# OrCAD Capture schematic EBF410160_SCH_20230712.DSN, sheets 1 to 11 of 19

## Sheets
1 12 WLAN BT: size A4; title: 野火_EBF RK3566 BTB 底板; rev: V1.0; note: WLAN & BT; note: https://yehuosm.tmall.com
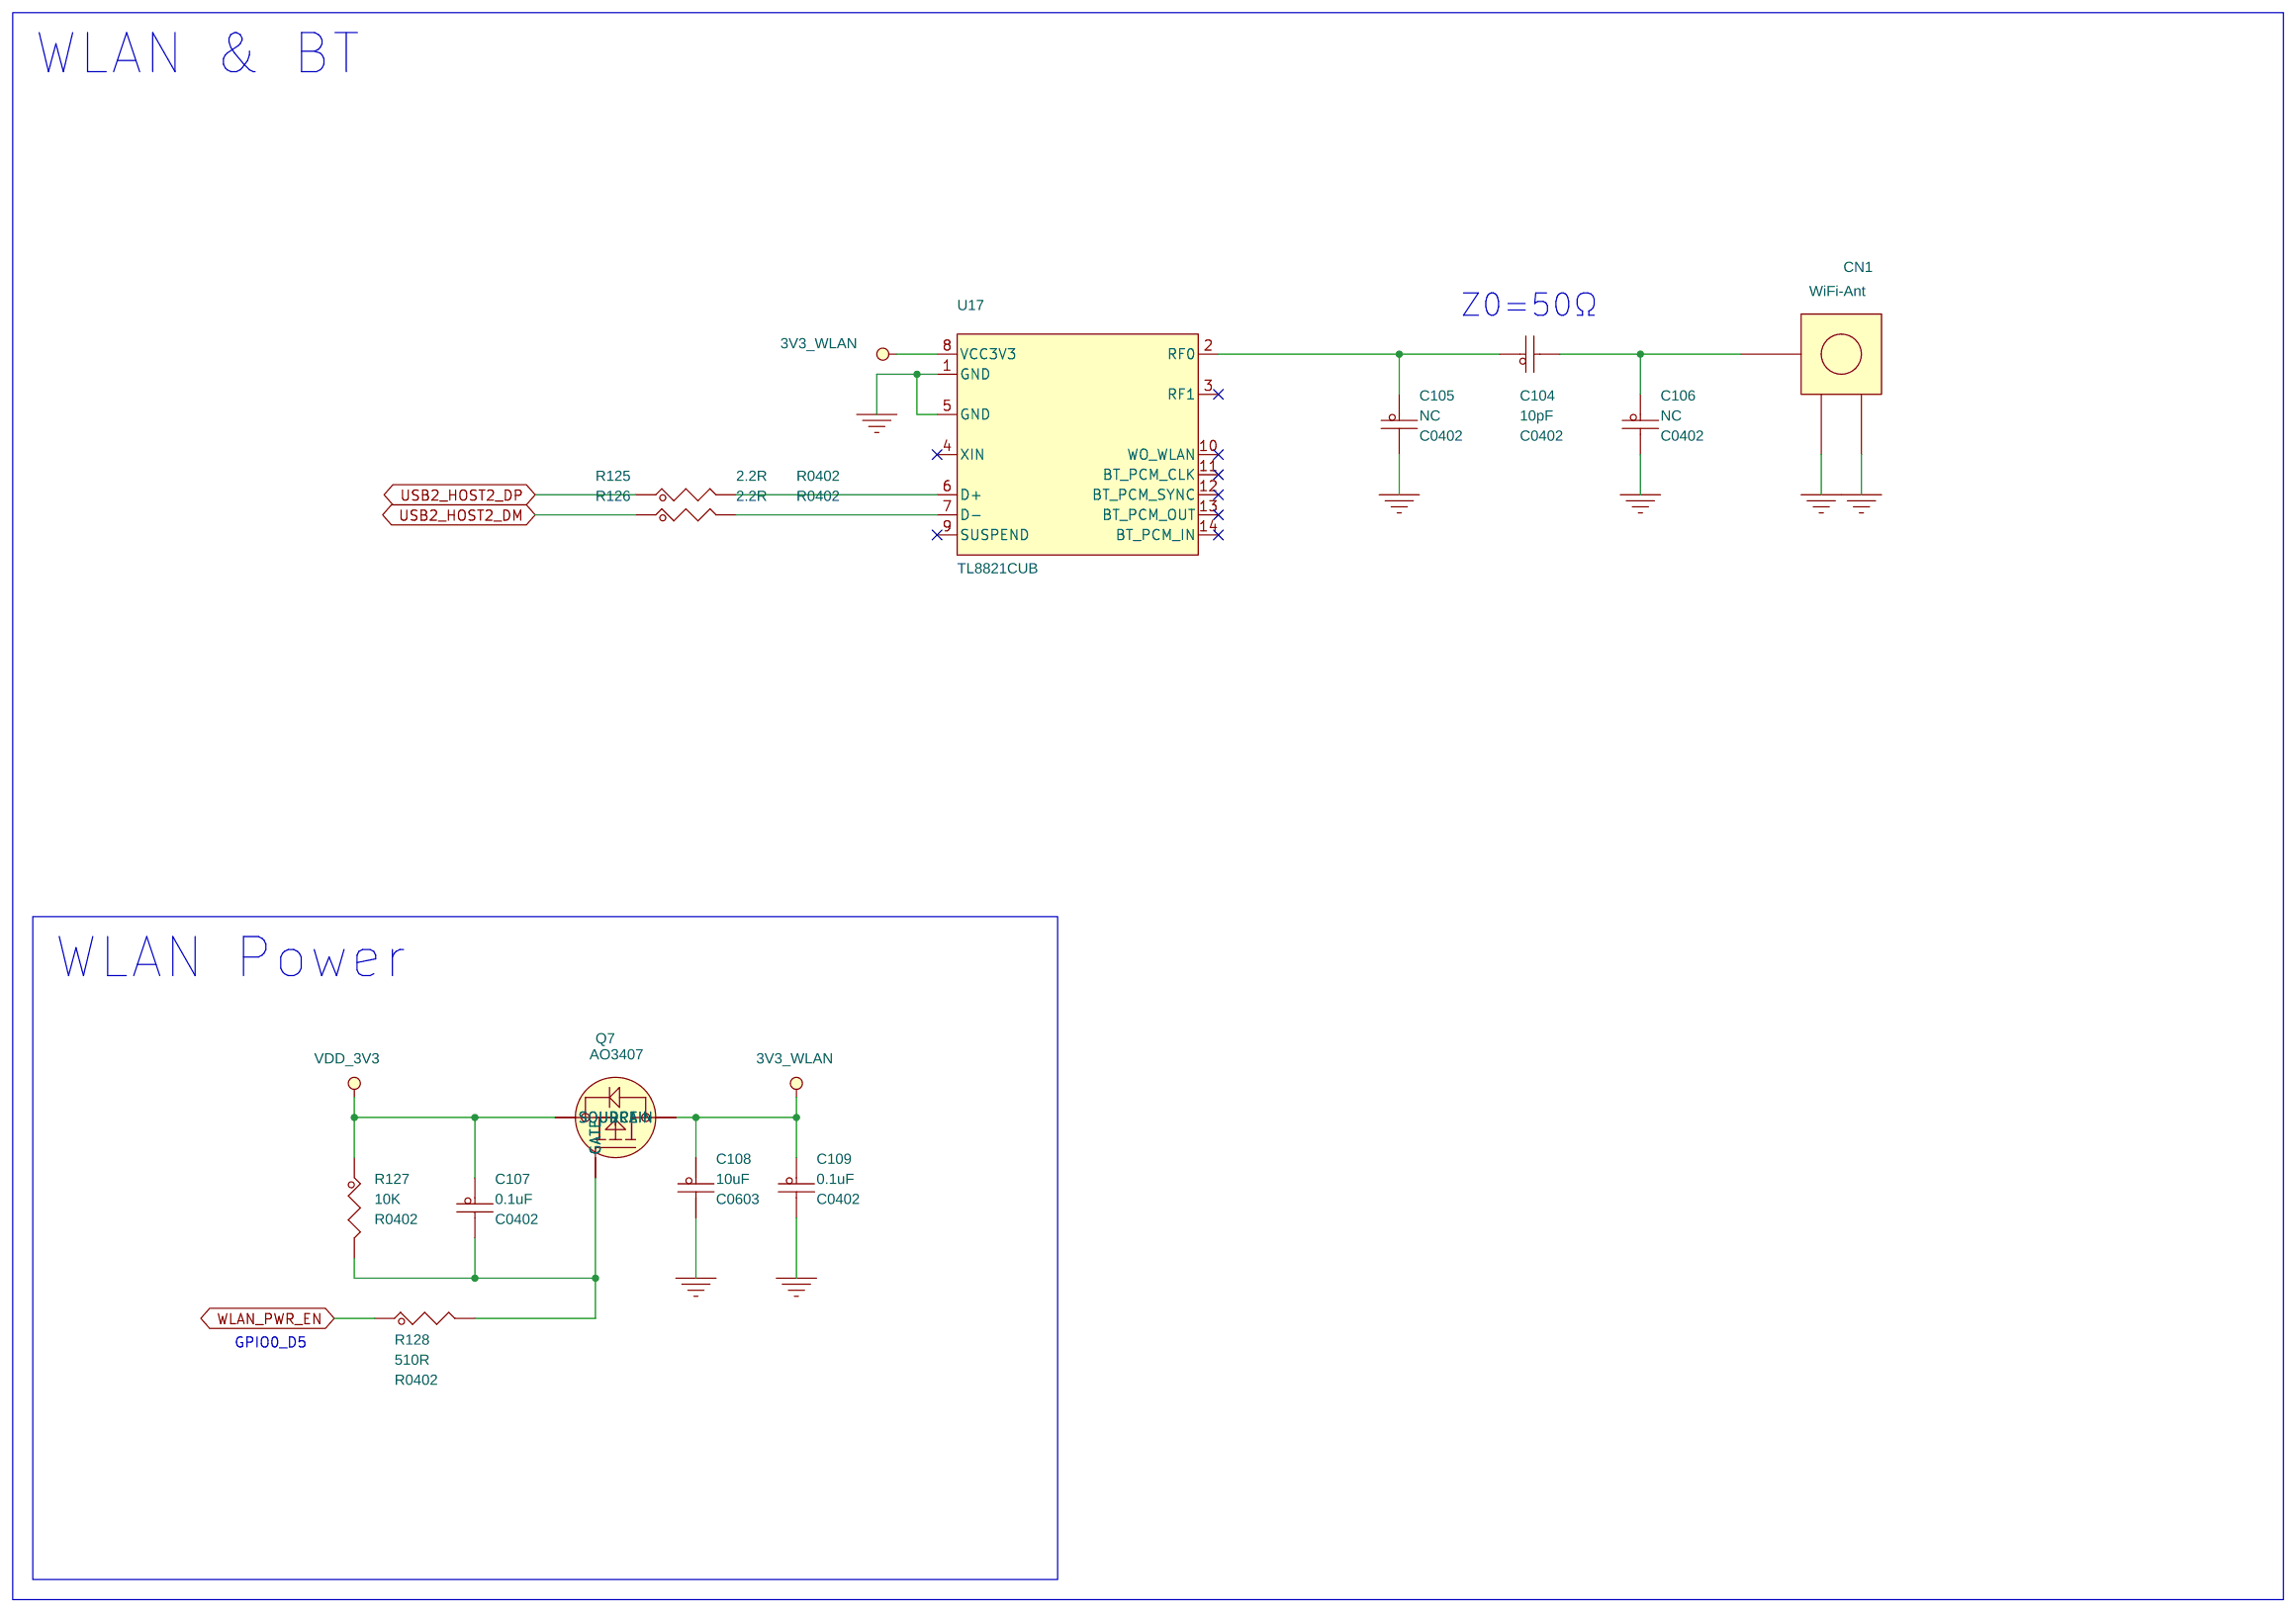
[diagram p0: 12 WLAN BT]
2 01 Content: note: Content
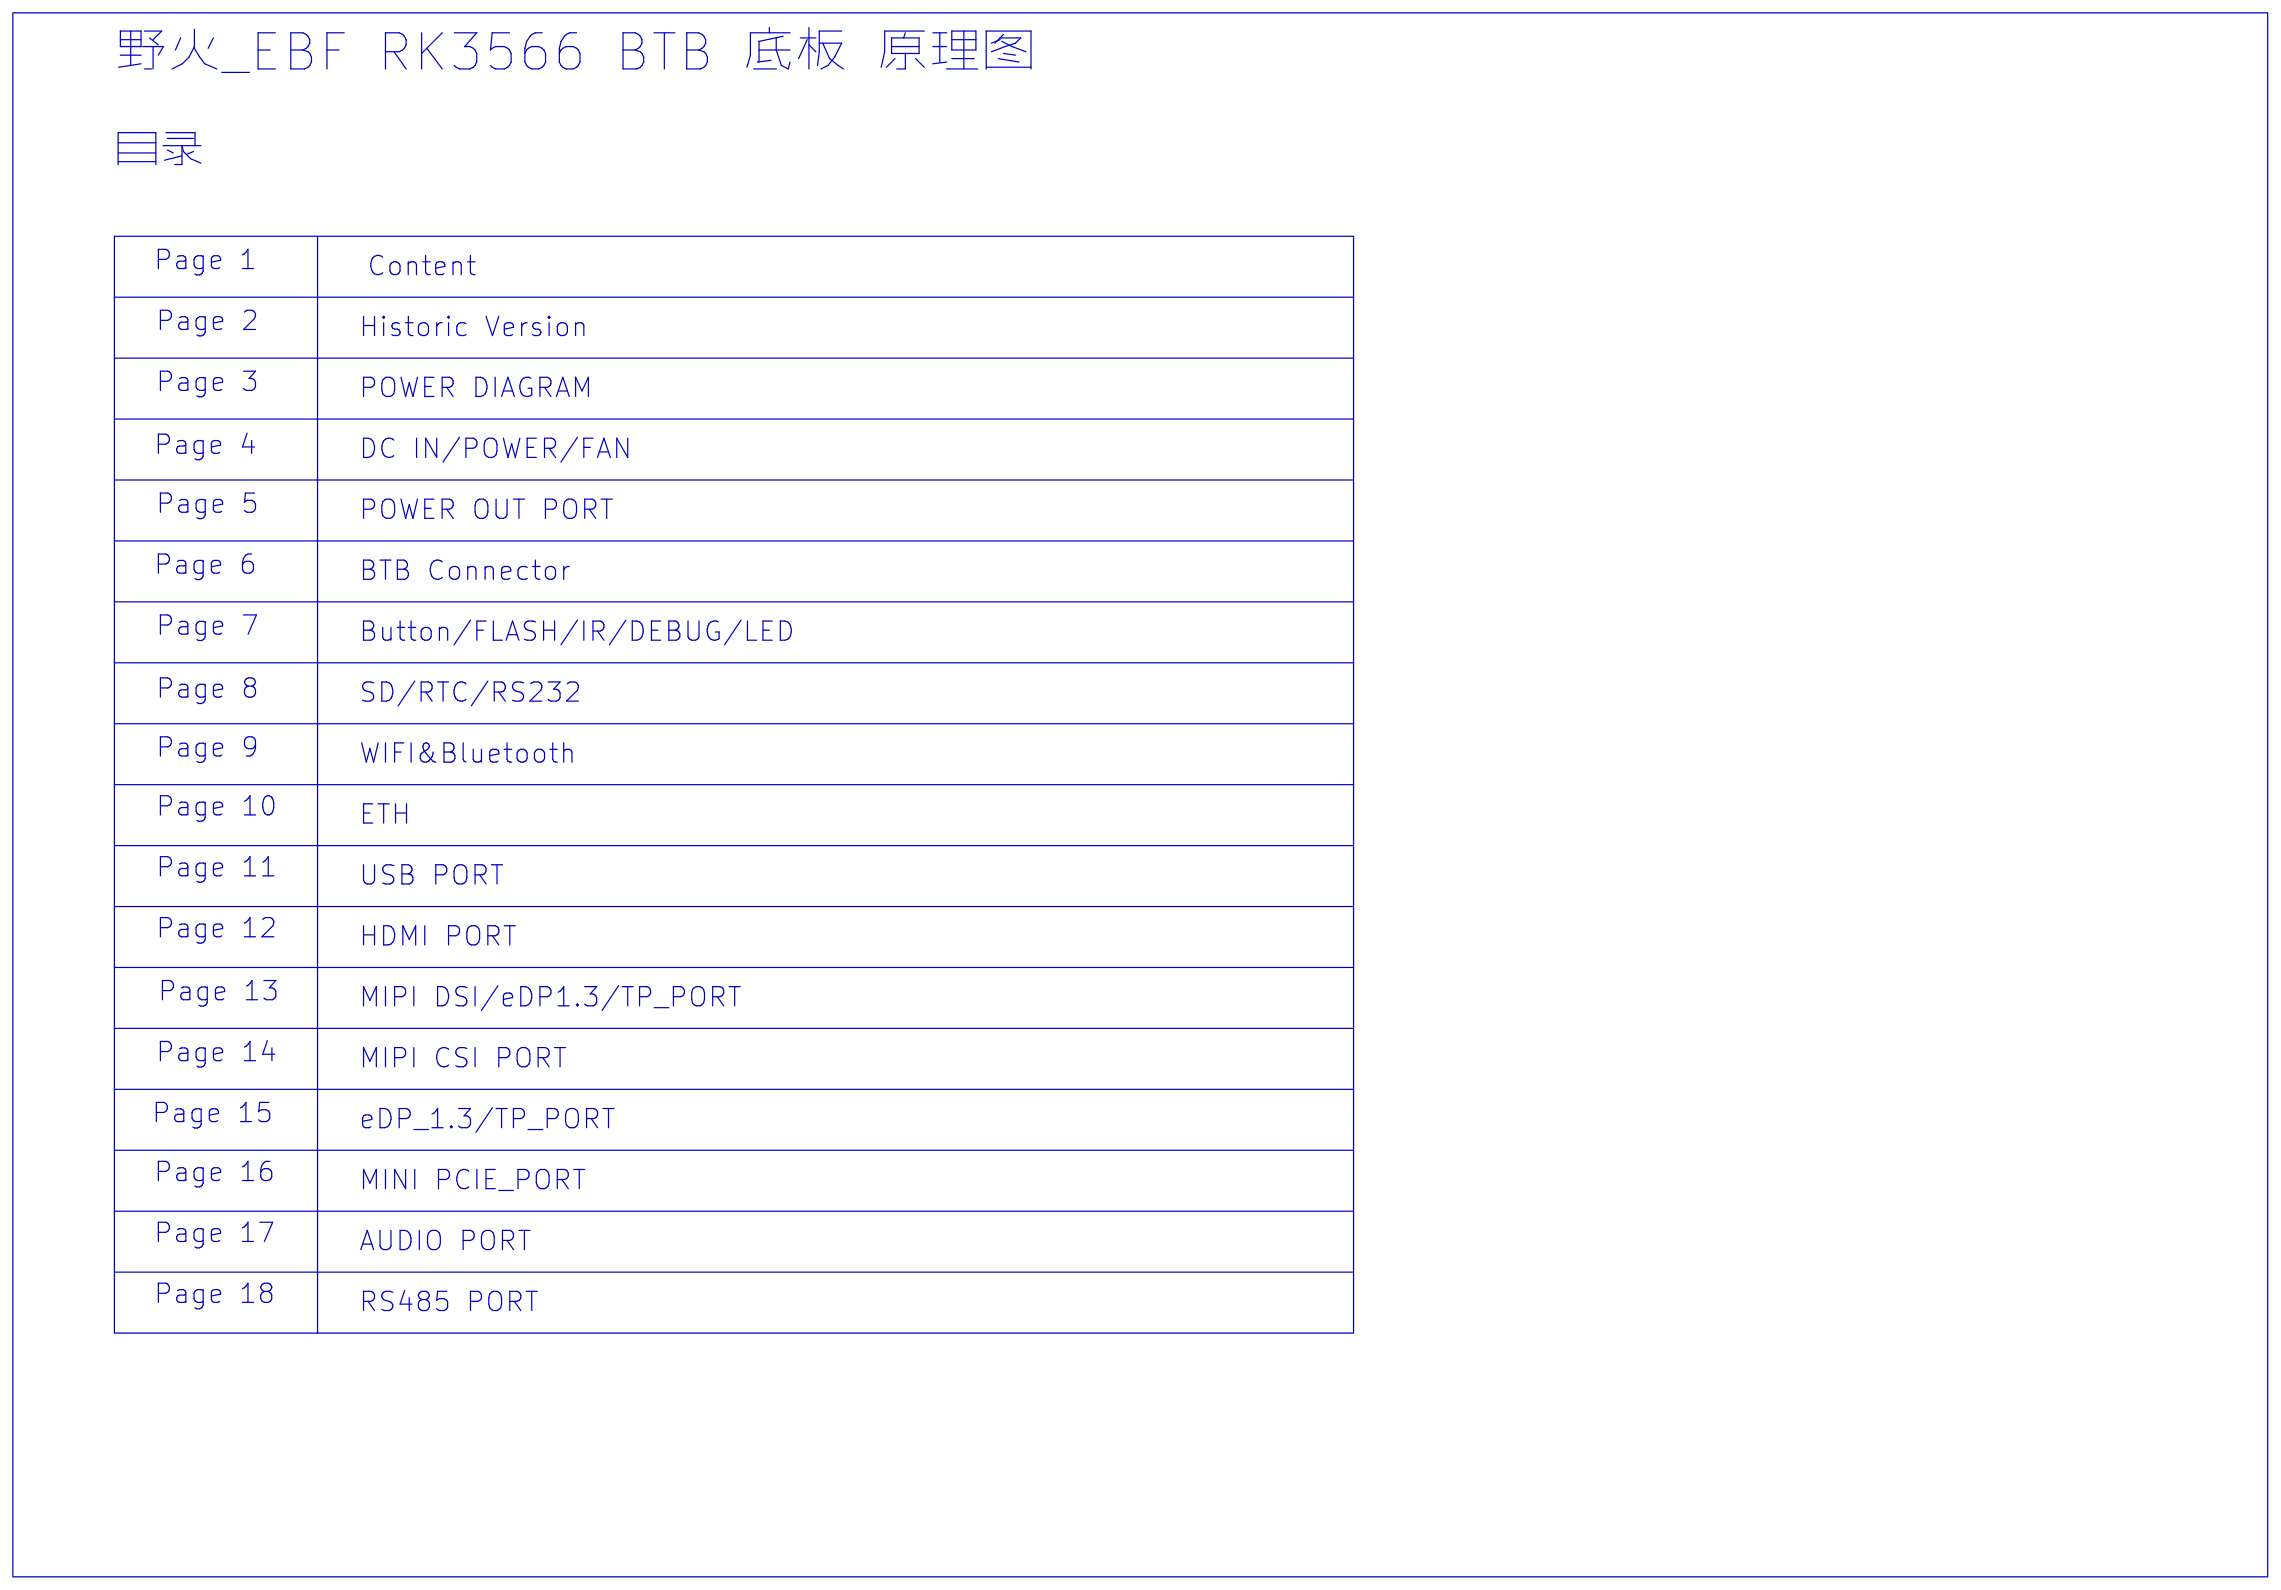
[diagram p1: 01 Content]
3 02 Historic Version: note: Historic Version
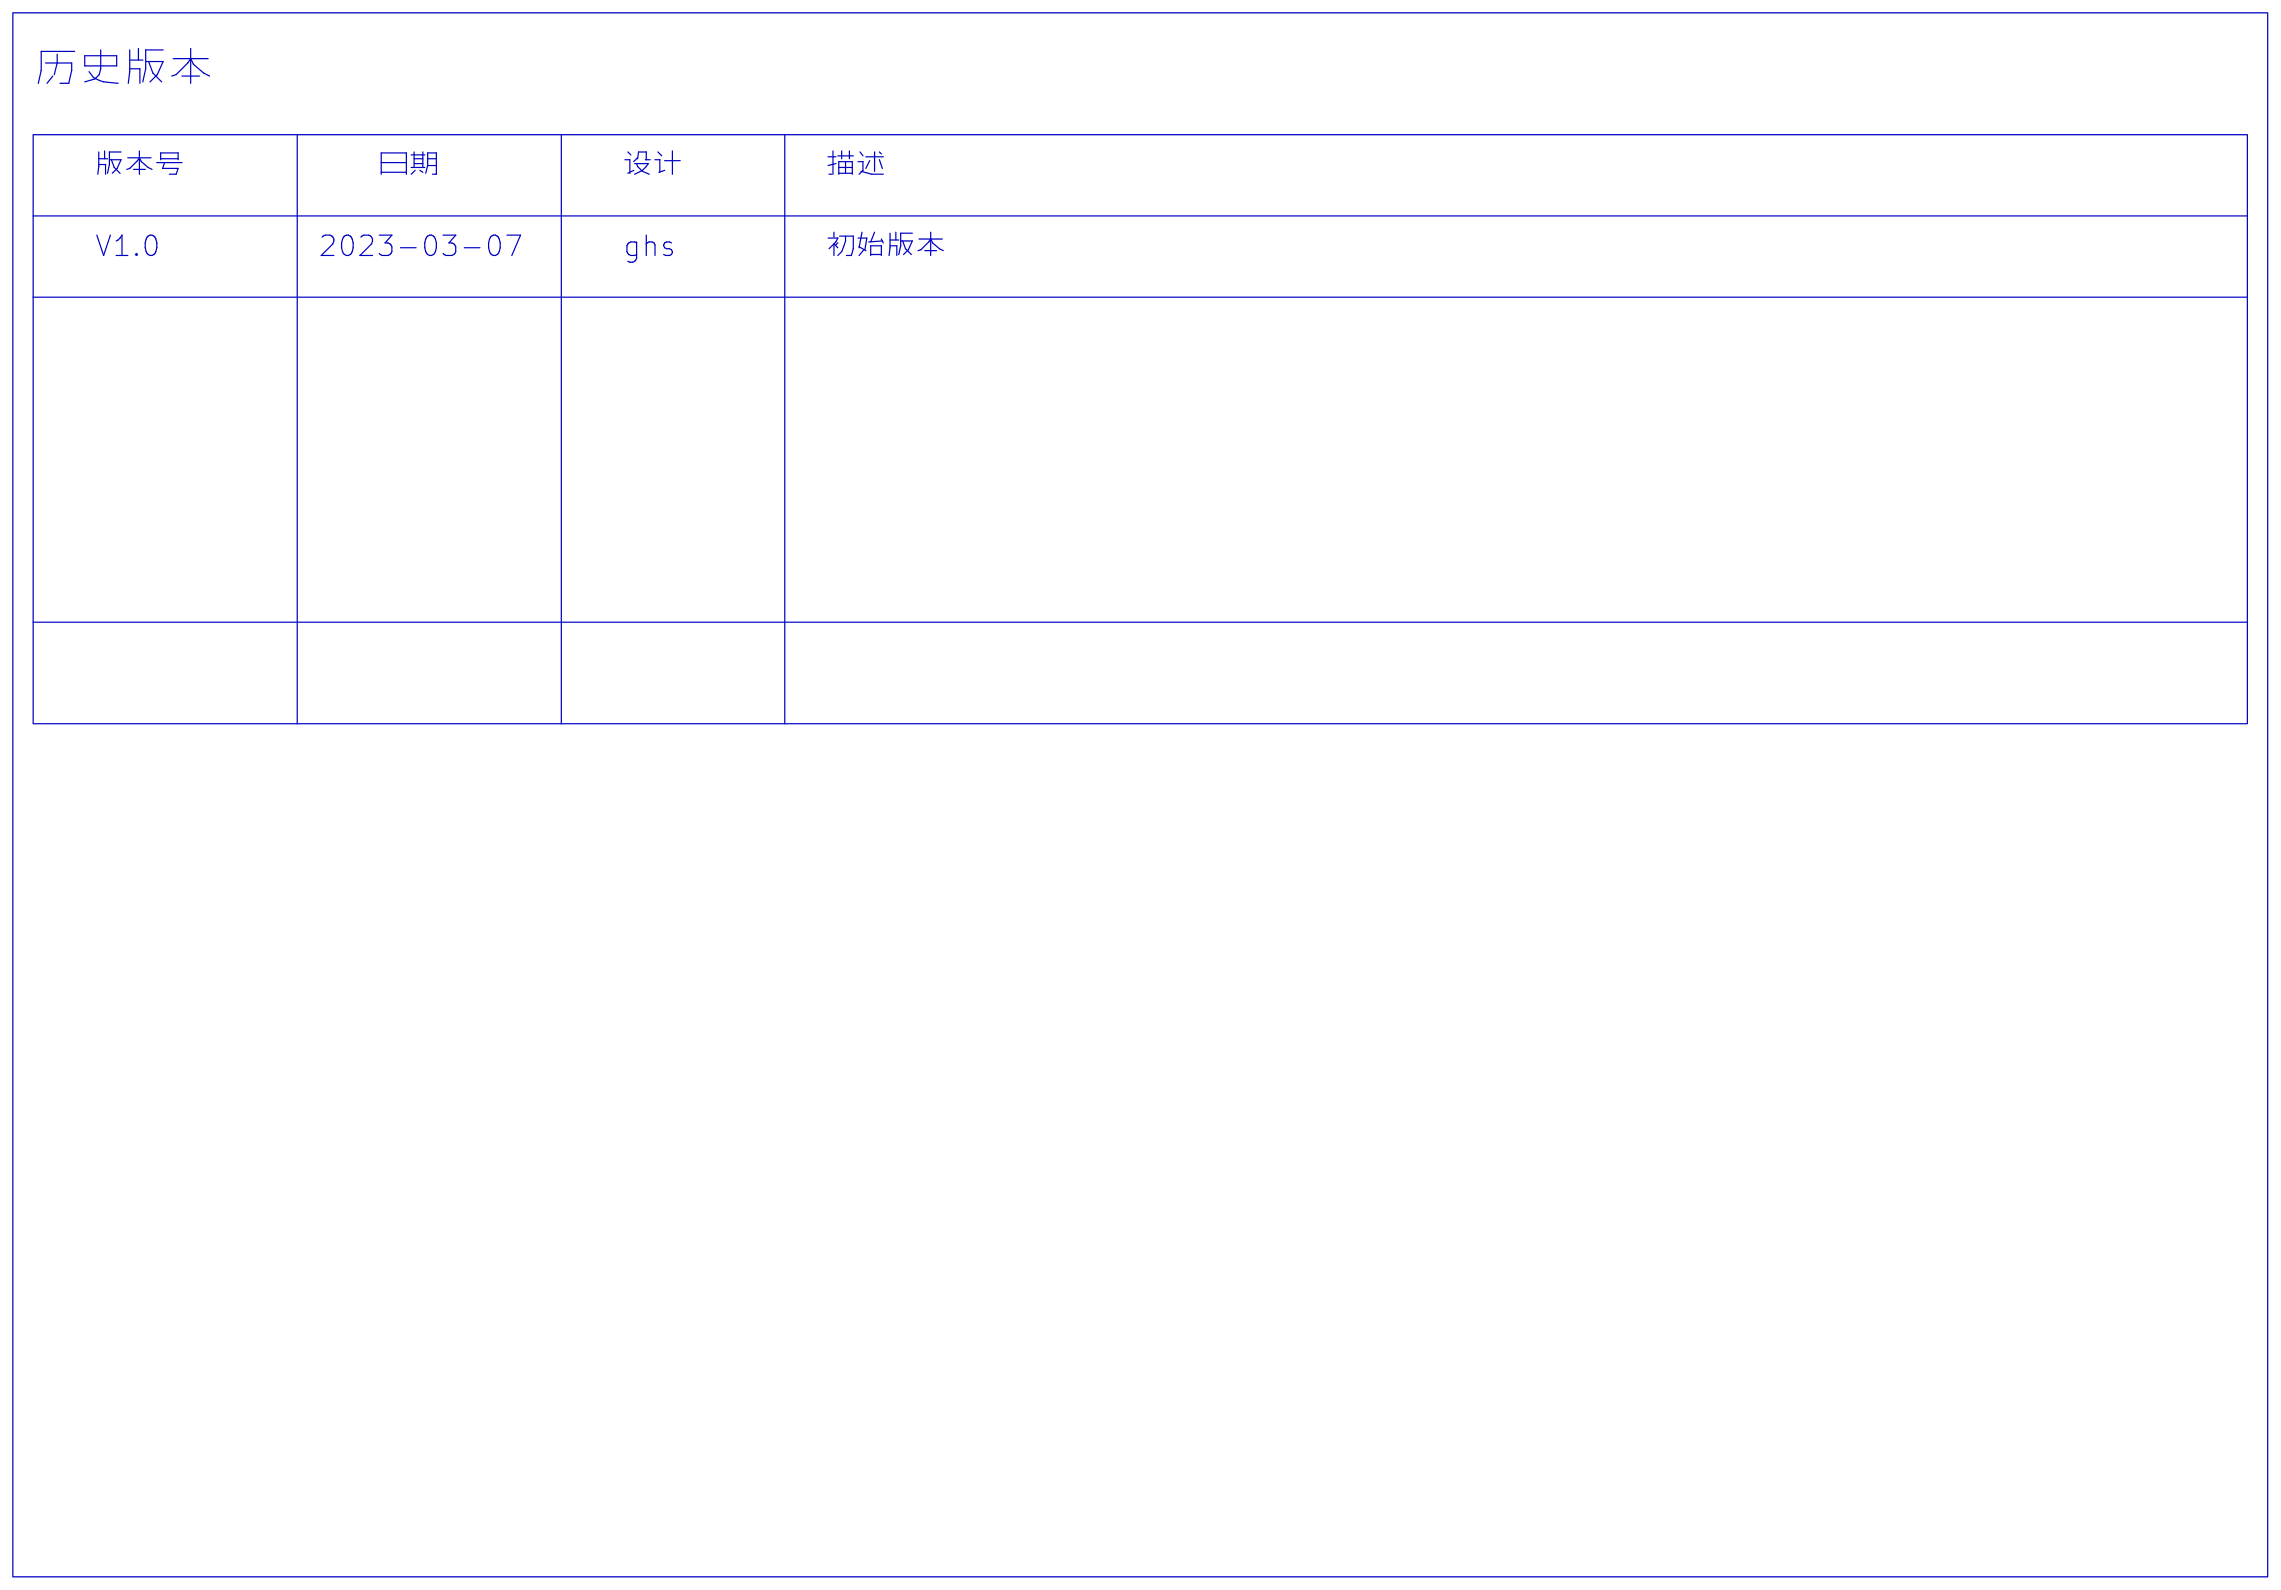
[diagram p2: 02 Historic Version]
4 03 POWER DIAGRAM: note: POWER DIAGRAM
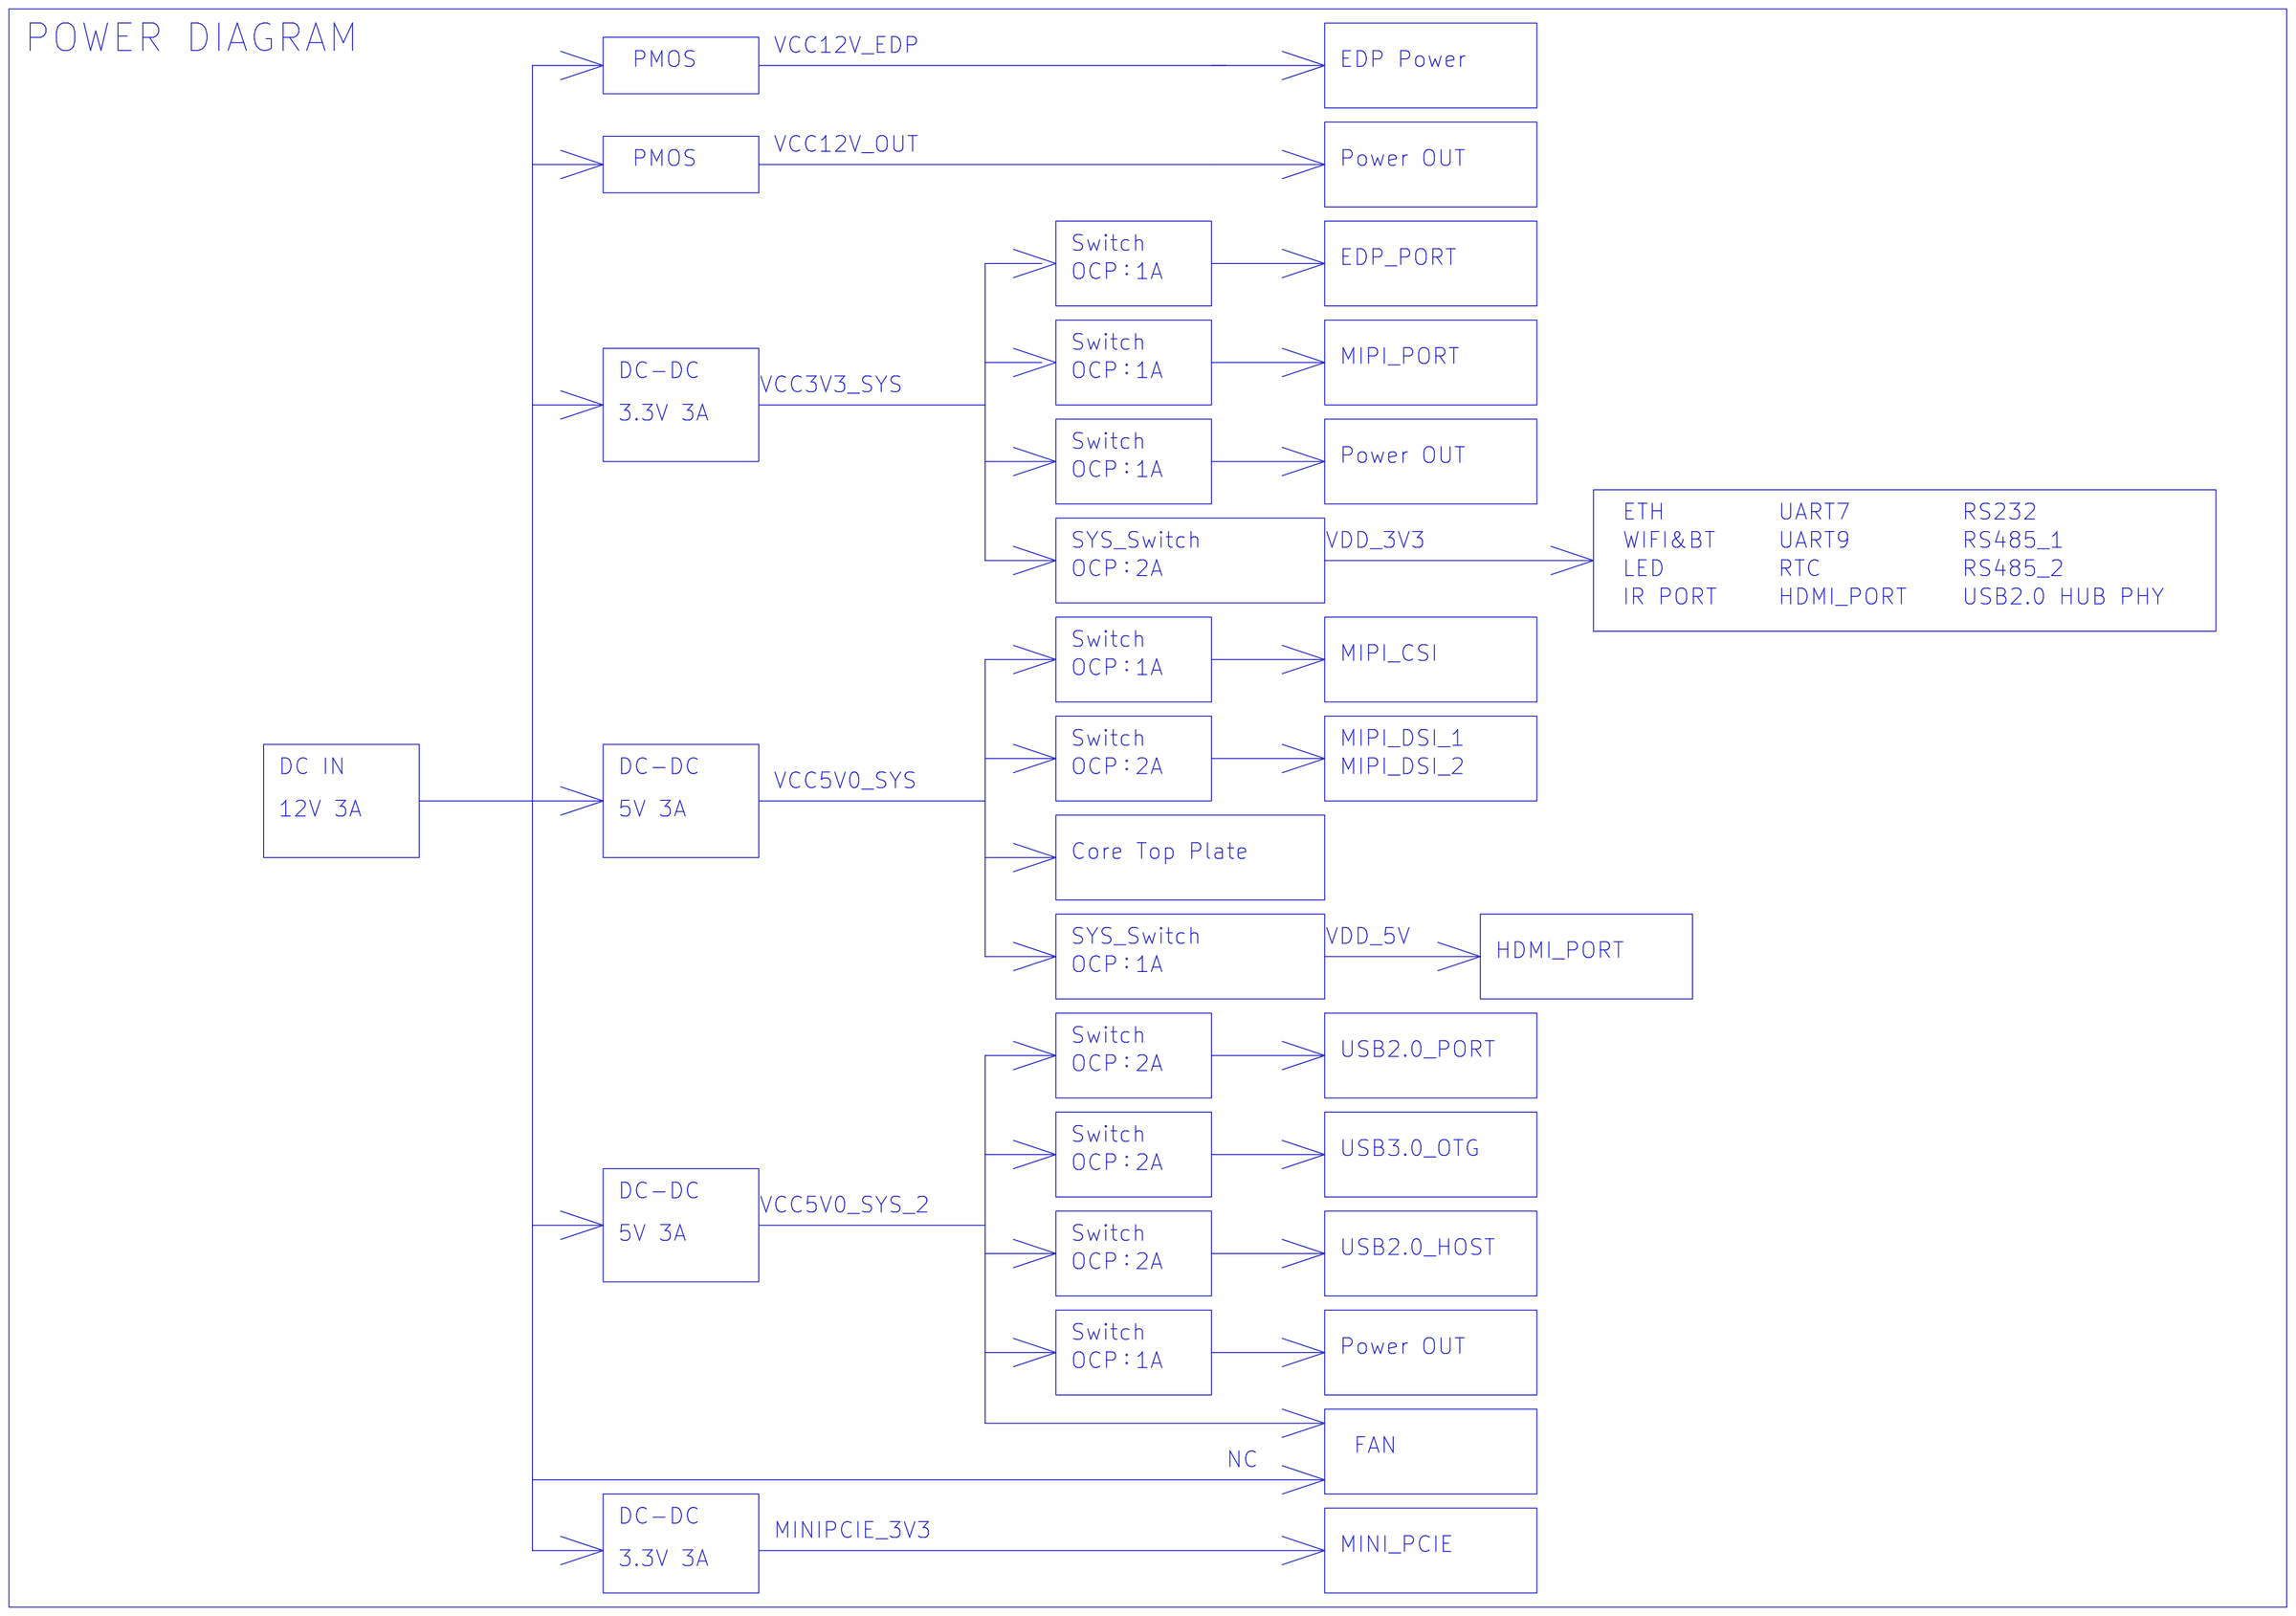
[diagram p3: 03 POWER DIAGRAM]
5 05 POWER OUT PORT: size A4; note: POWER OUT PORT
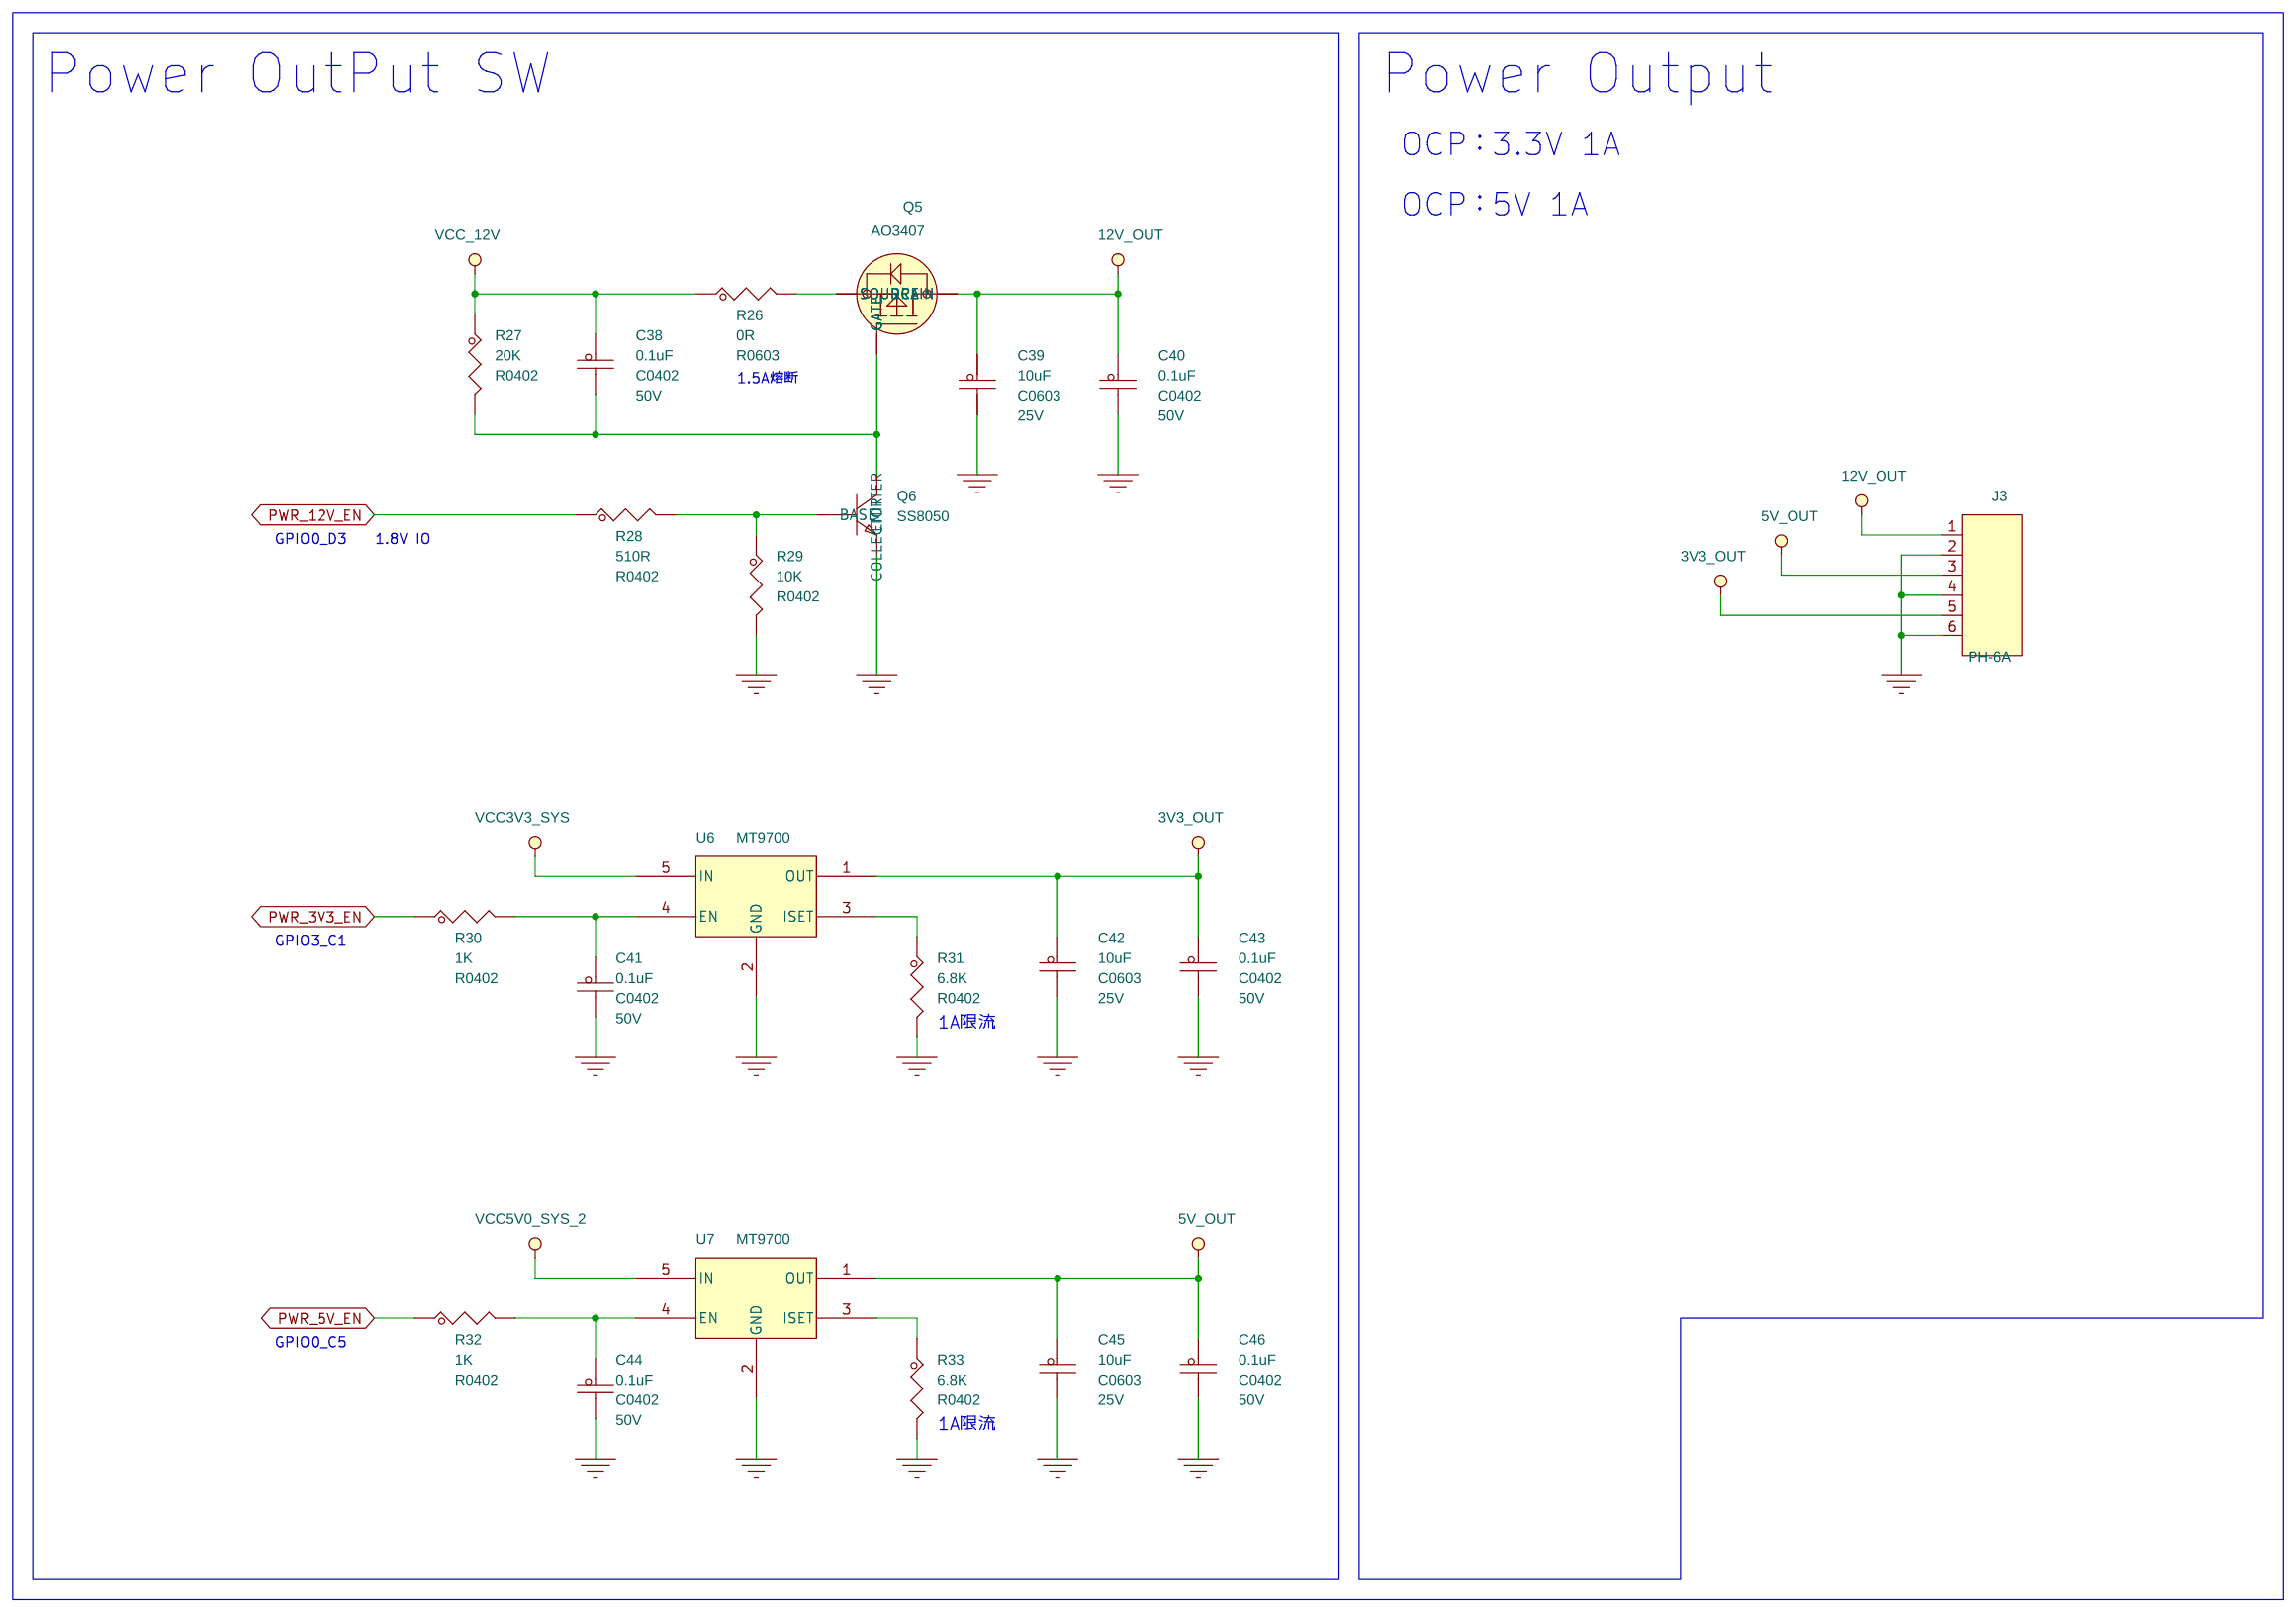
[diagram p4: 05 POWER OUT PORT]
6 06 BTB Connector: size A3; title: 野火_EBF RK3568 BTB 底板; note: BTB Connector
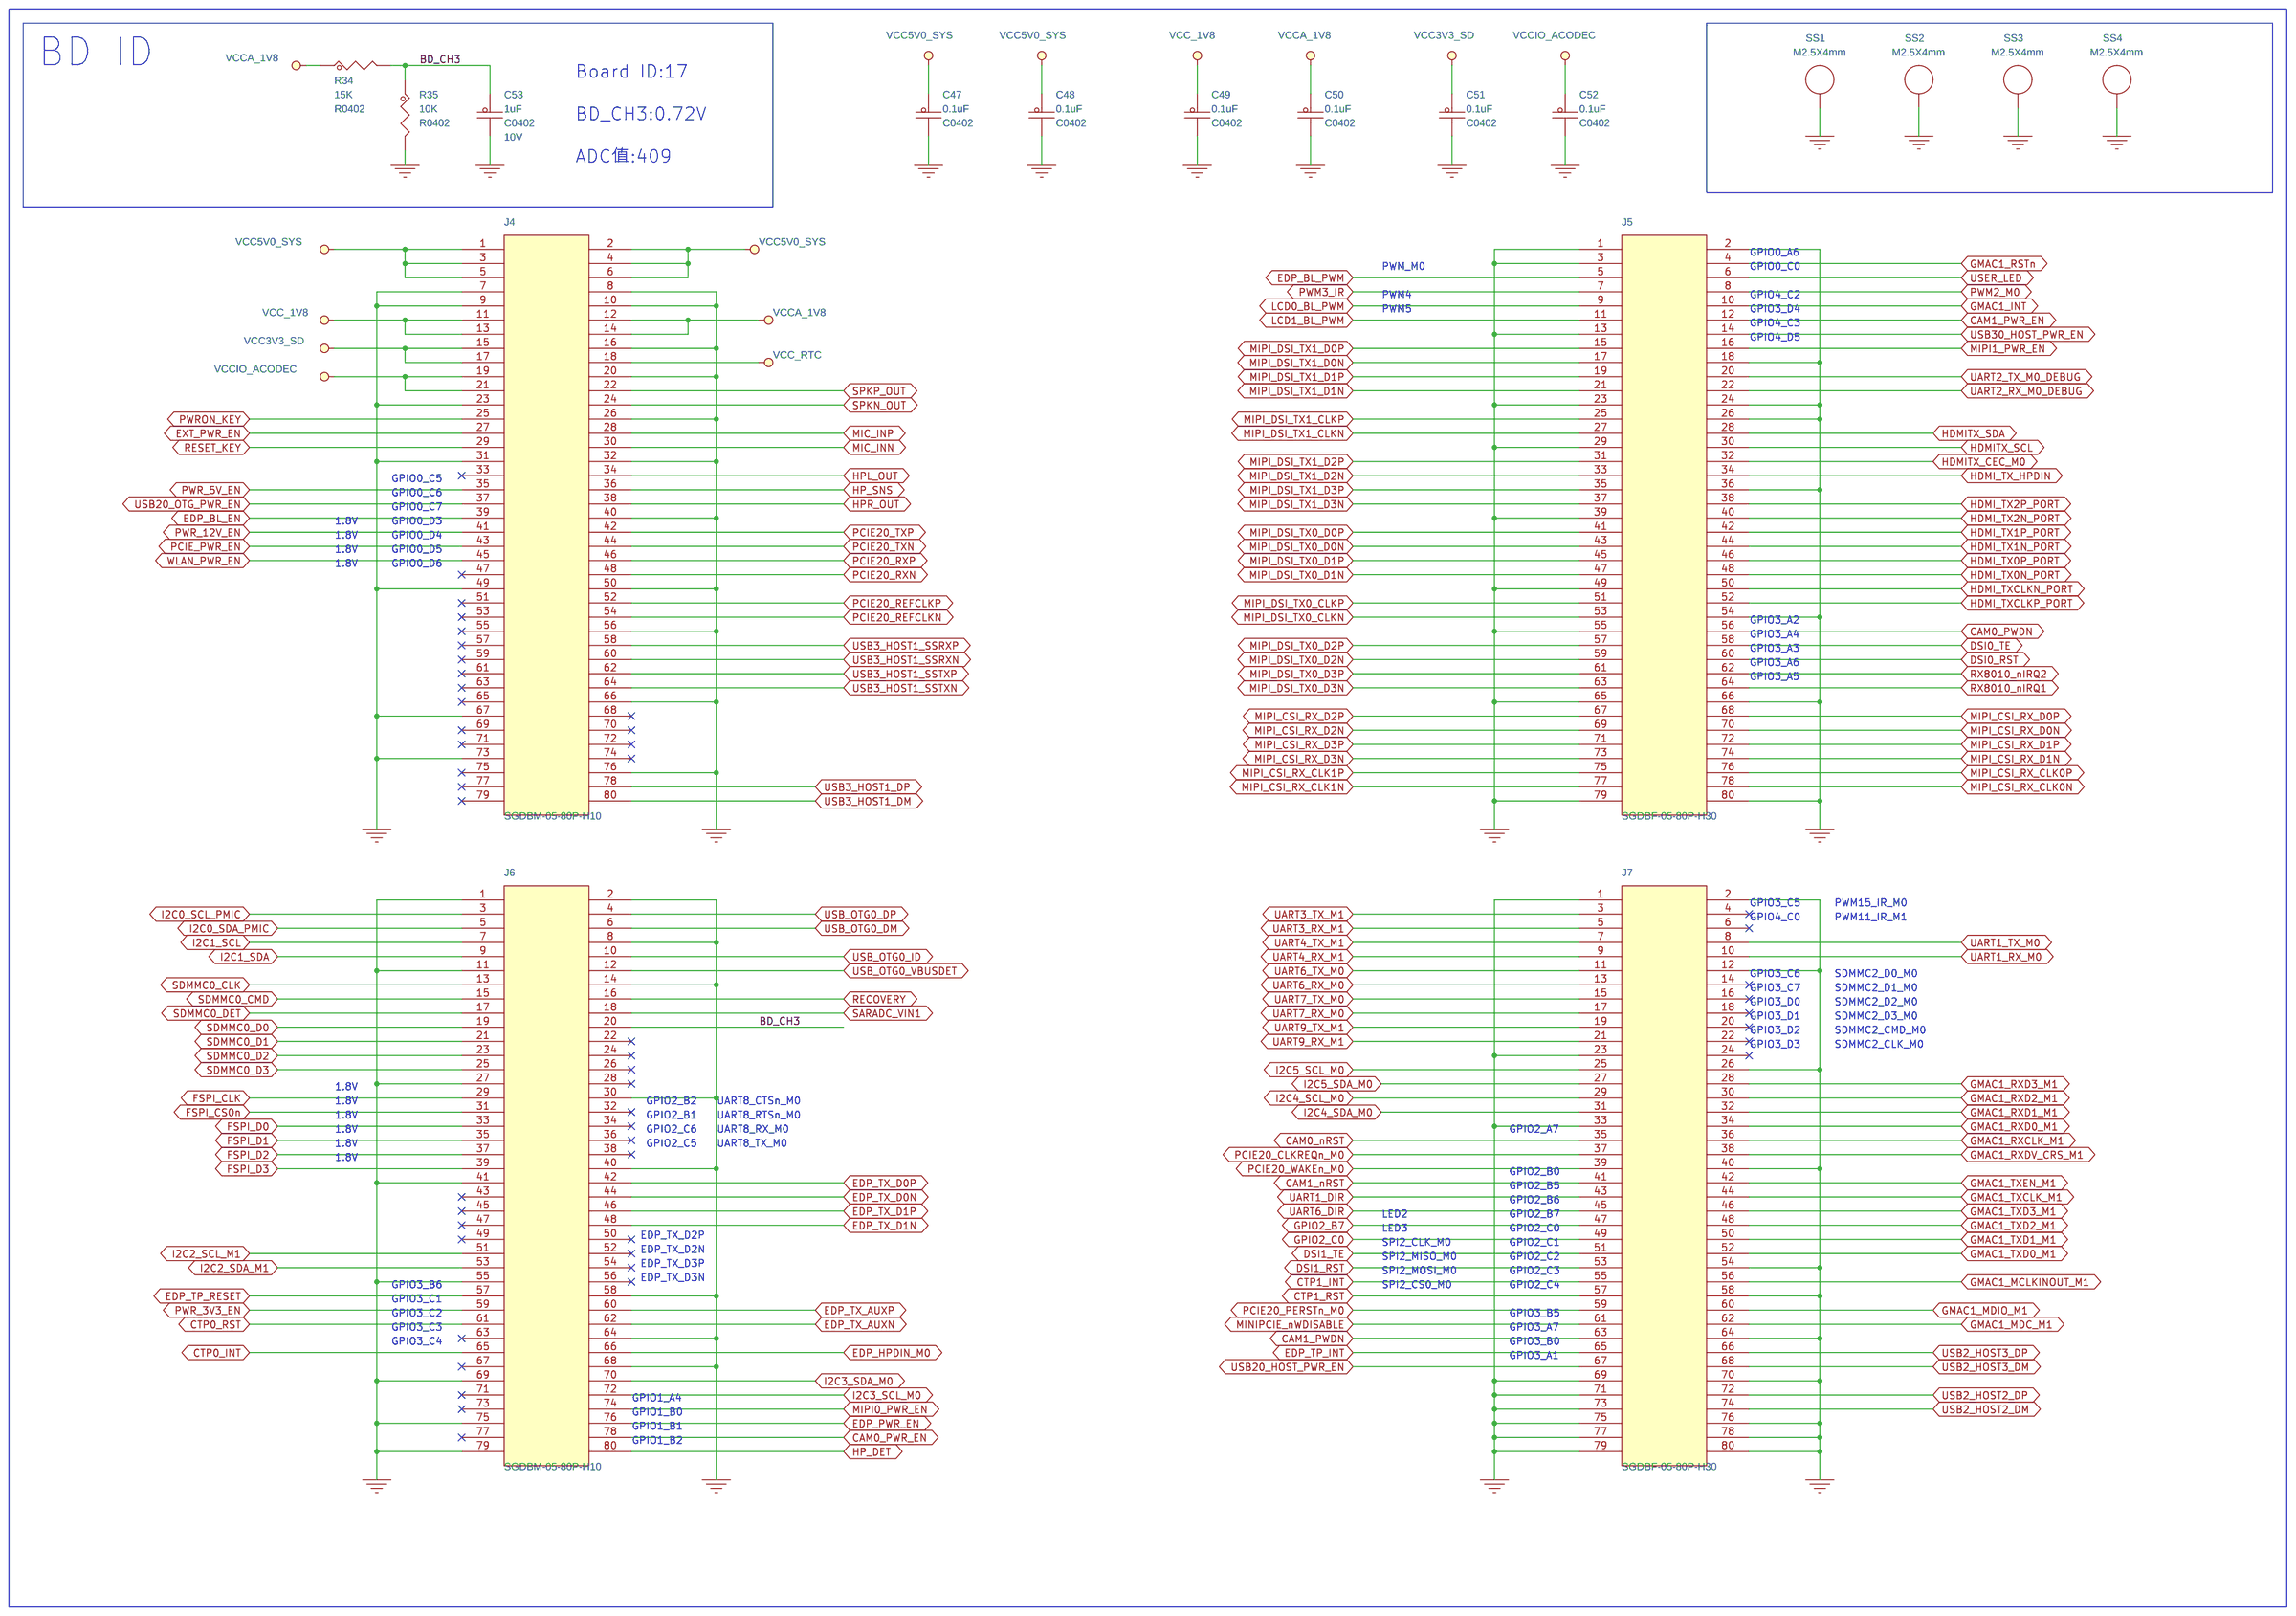
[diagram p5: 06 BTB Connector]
7 09 RS485 PORT: size A4; note: RS485 PORT
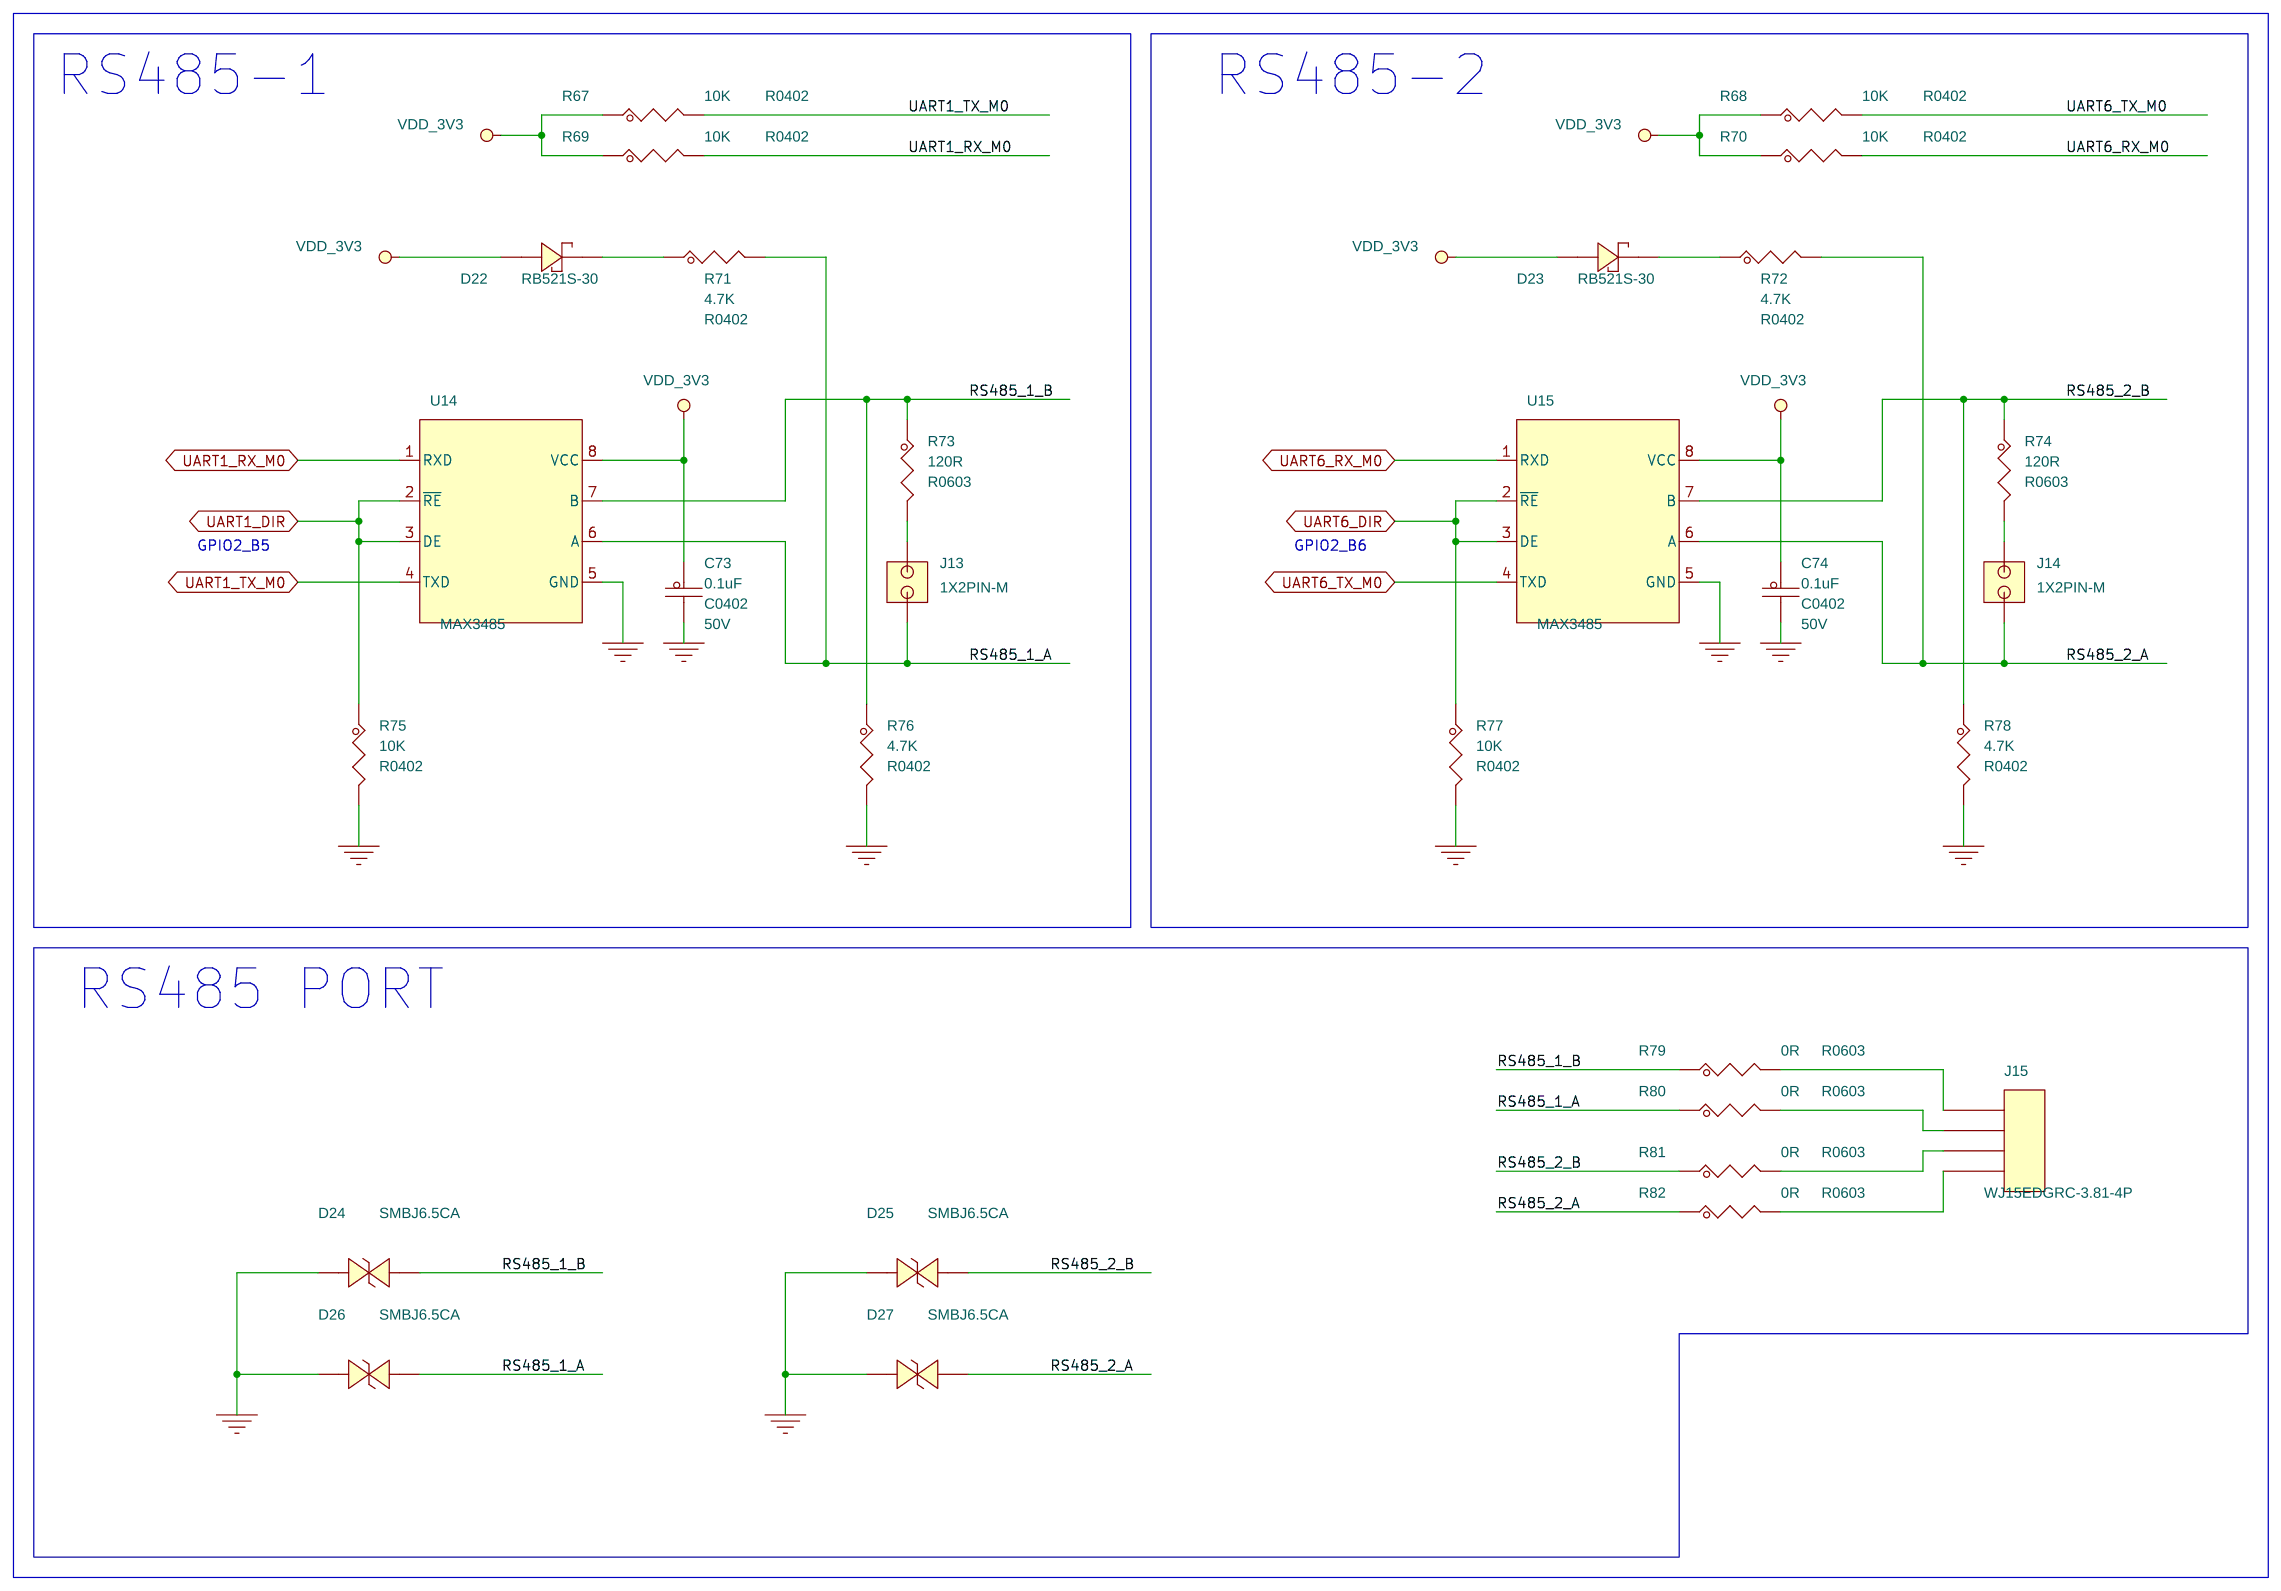
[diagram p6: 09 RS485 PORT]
8 11 ETH: size A3; note: ETH
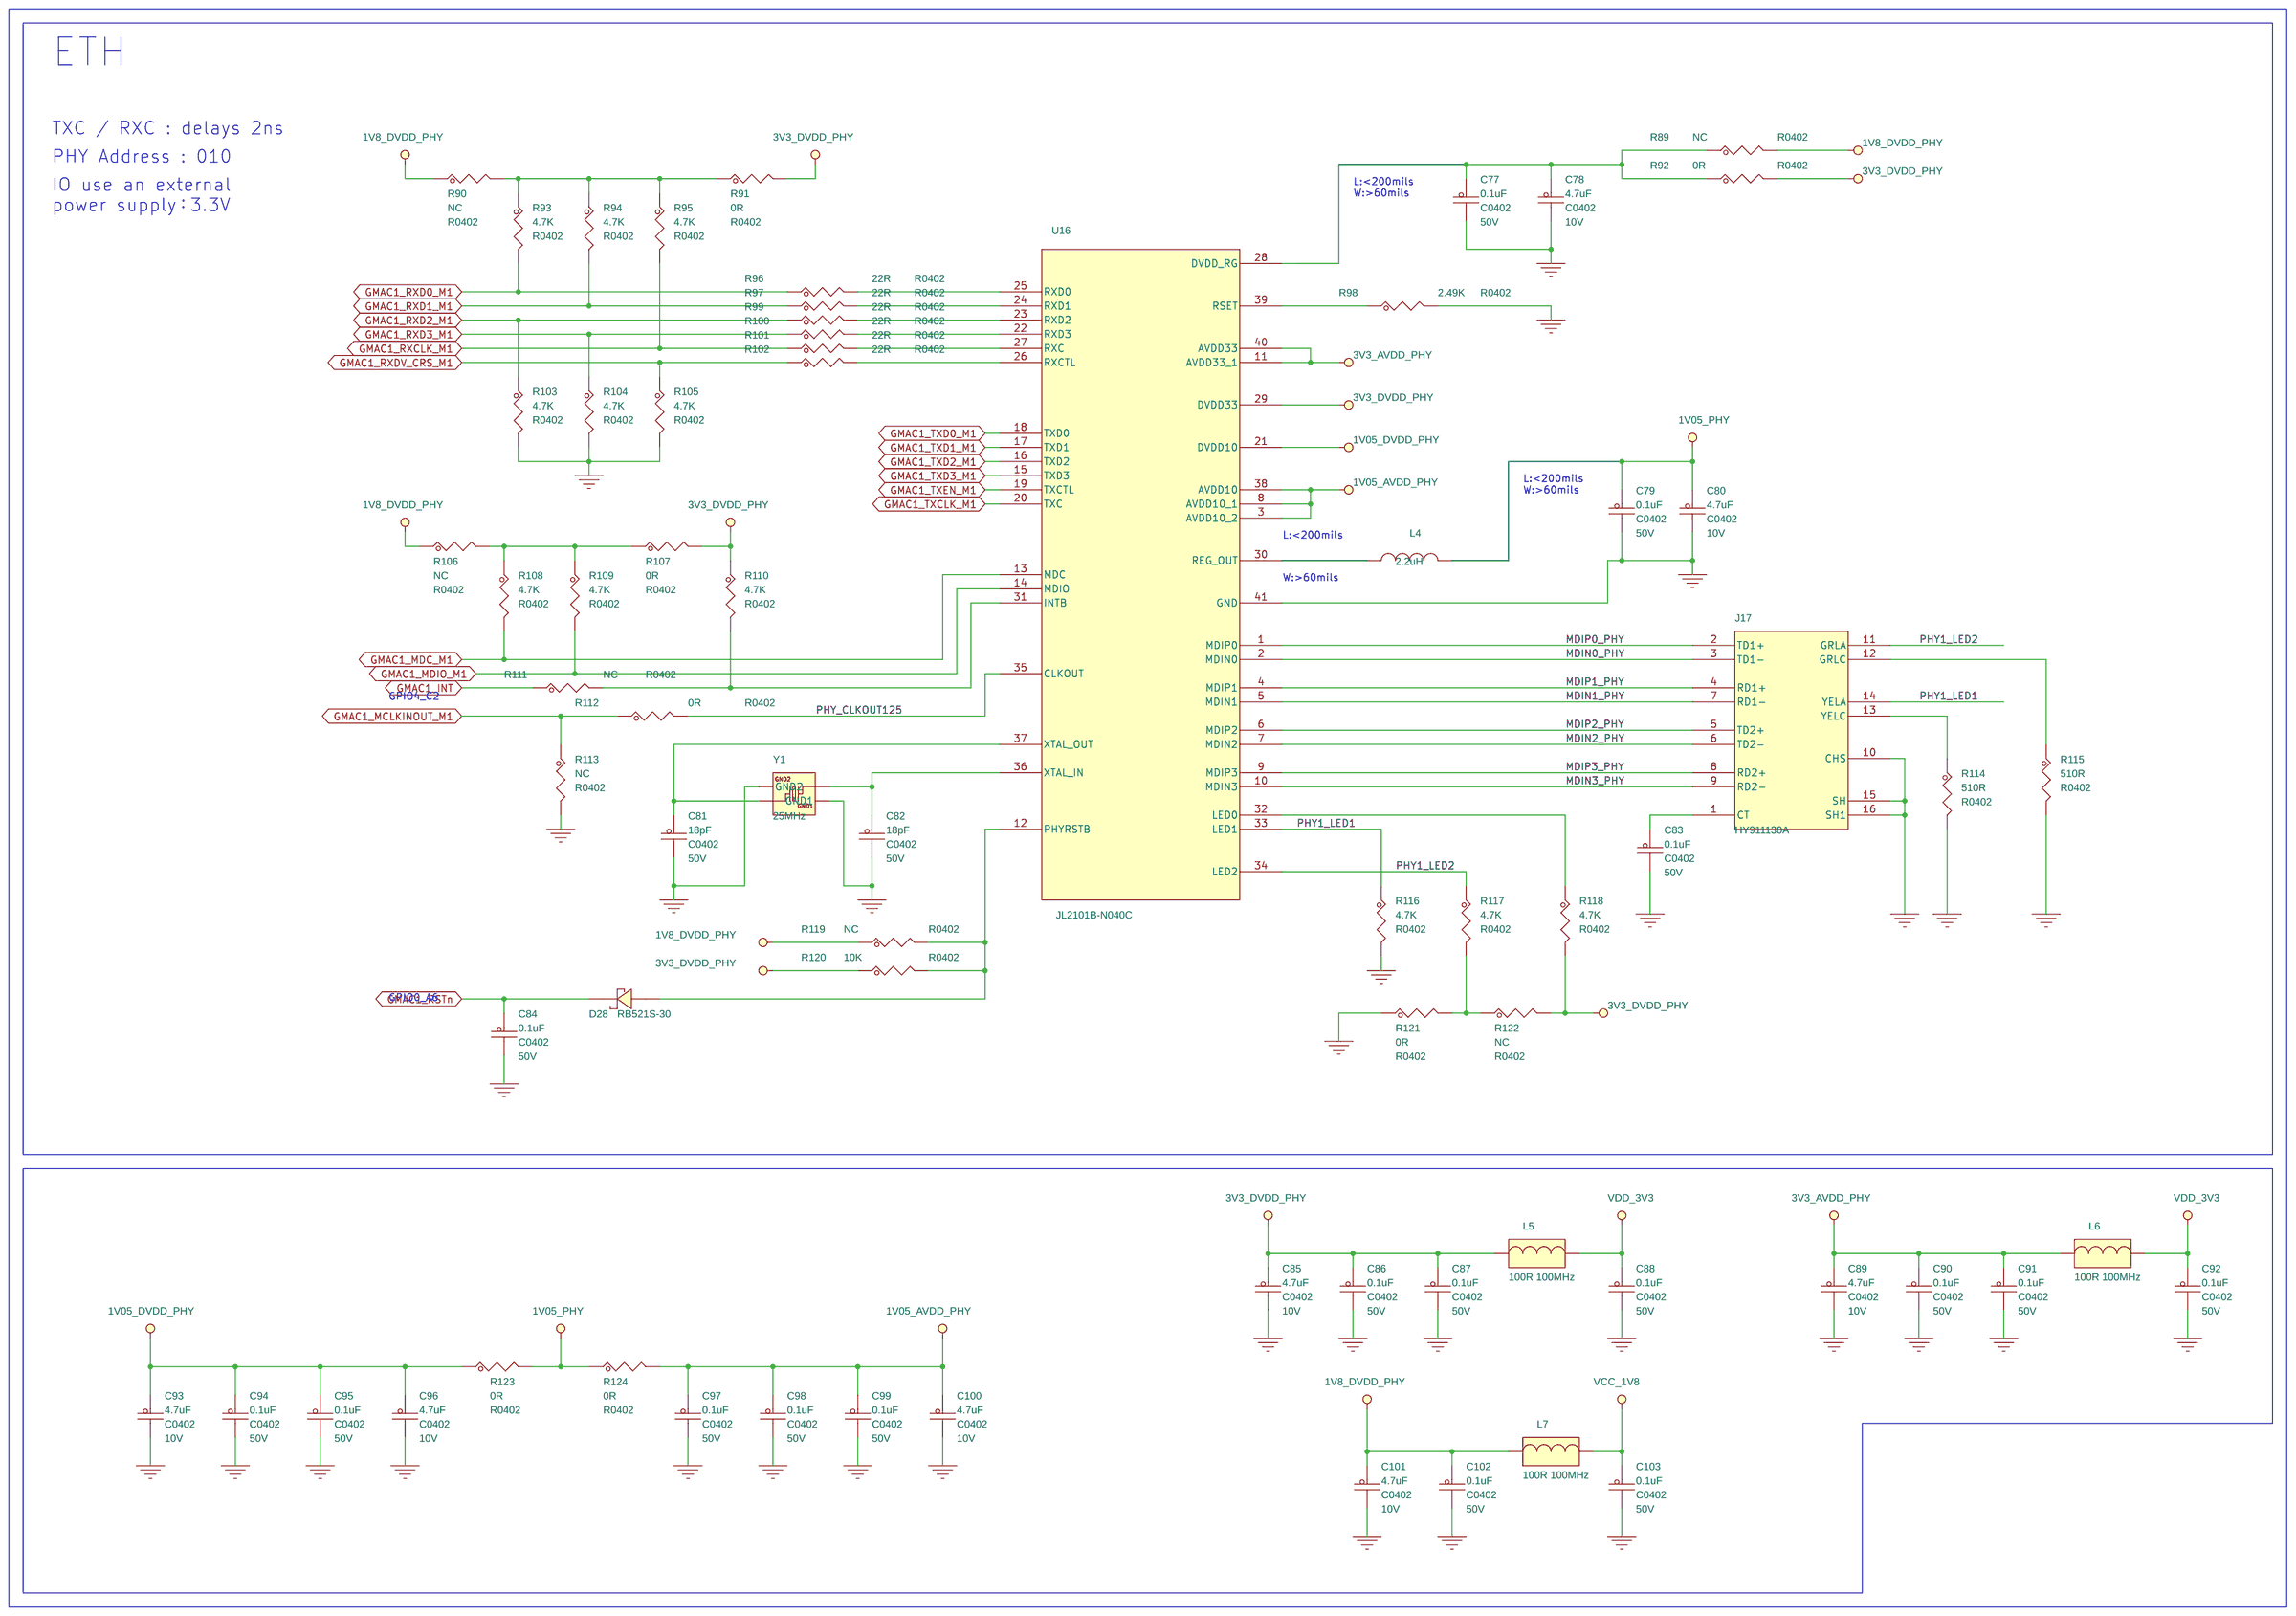
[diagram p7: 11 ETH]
9 13 USB PORT: size A3; note: USB PORT
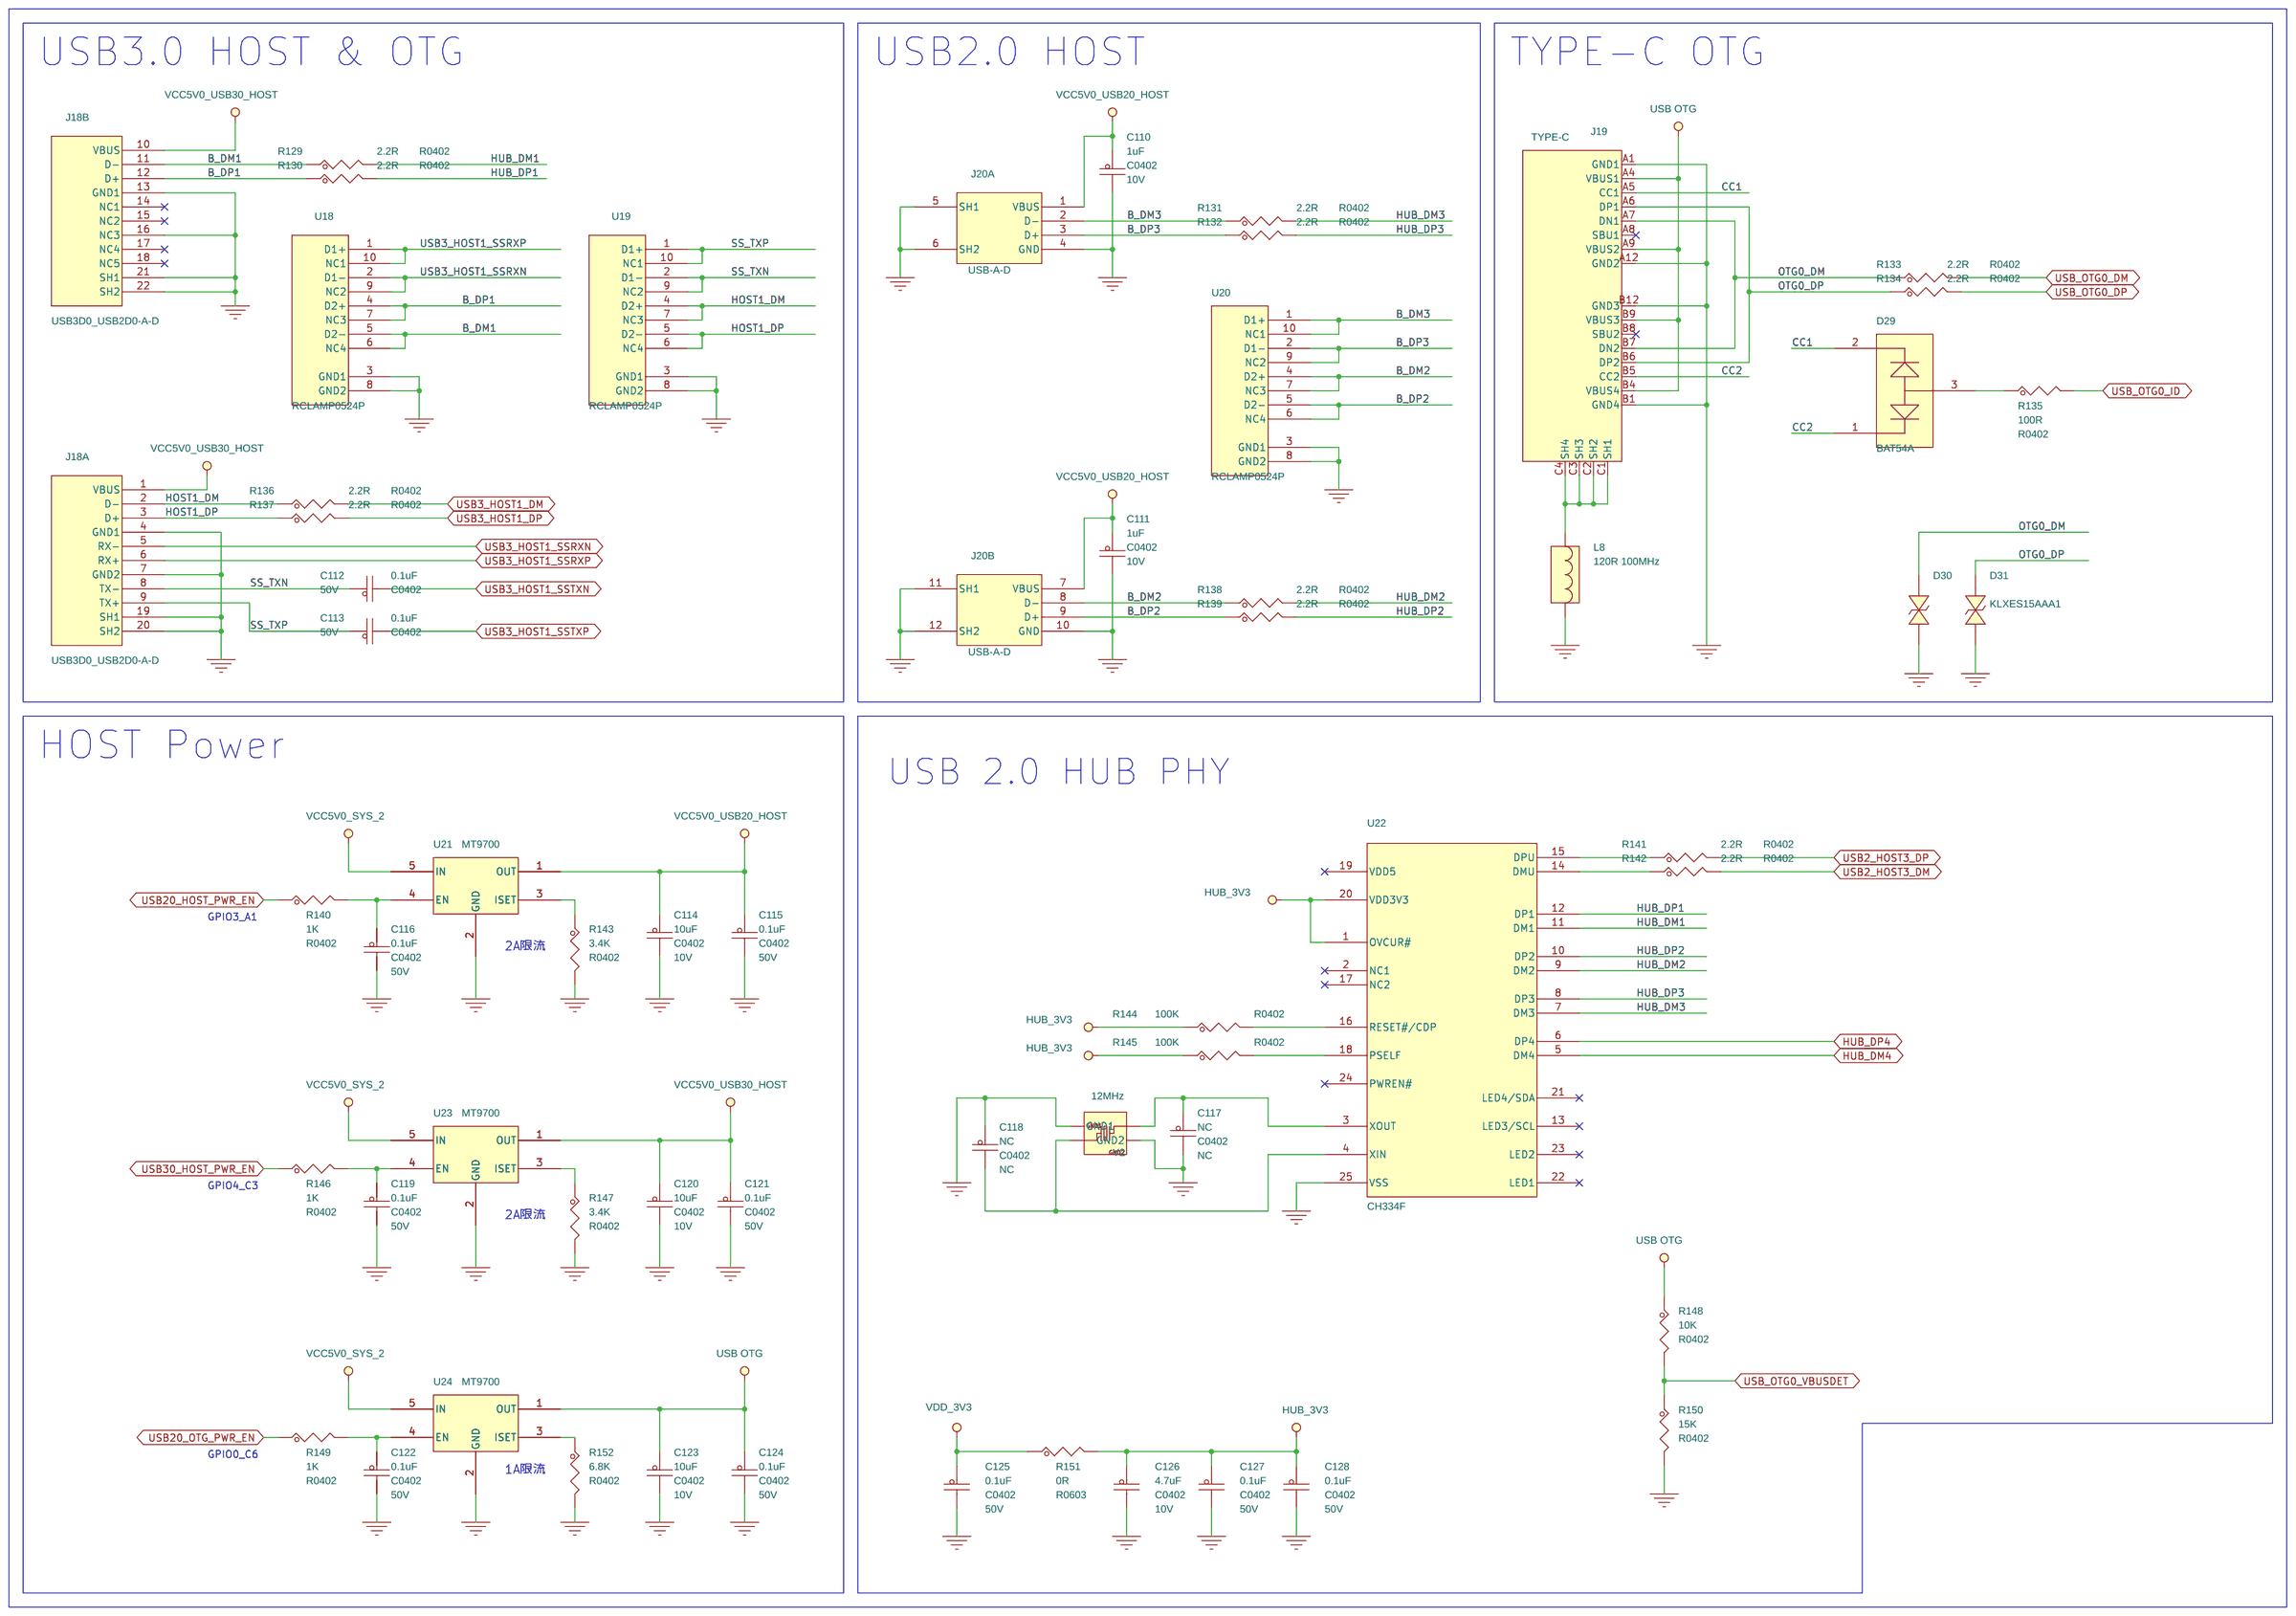
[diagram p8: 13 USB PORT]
10 14 HDMI PORT: size A4; note: HDMI PORT
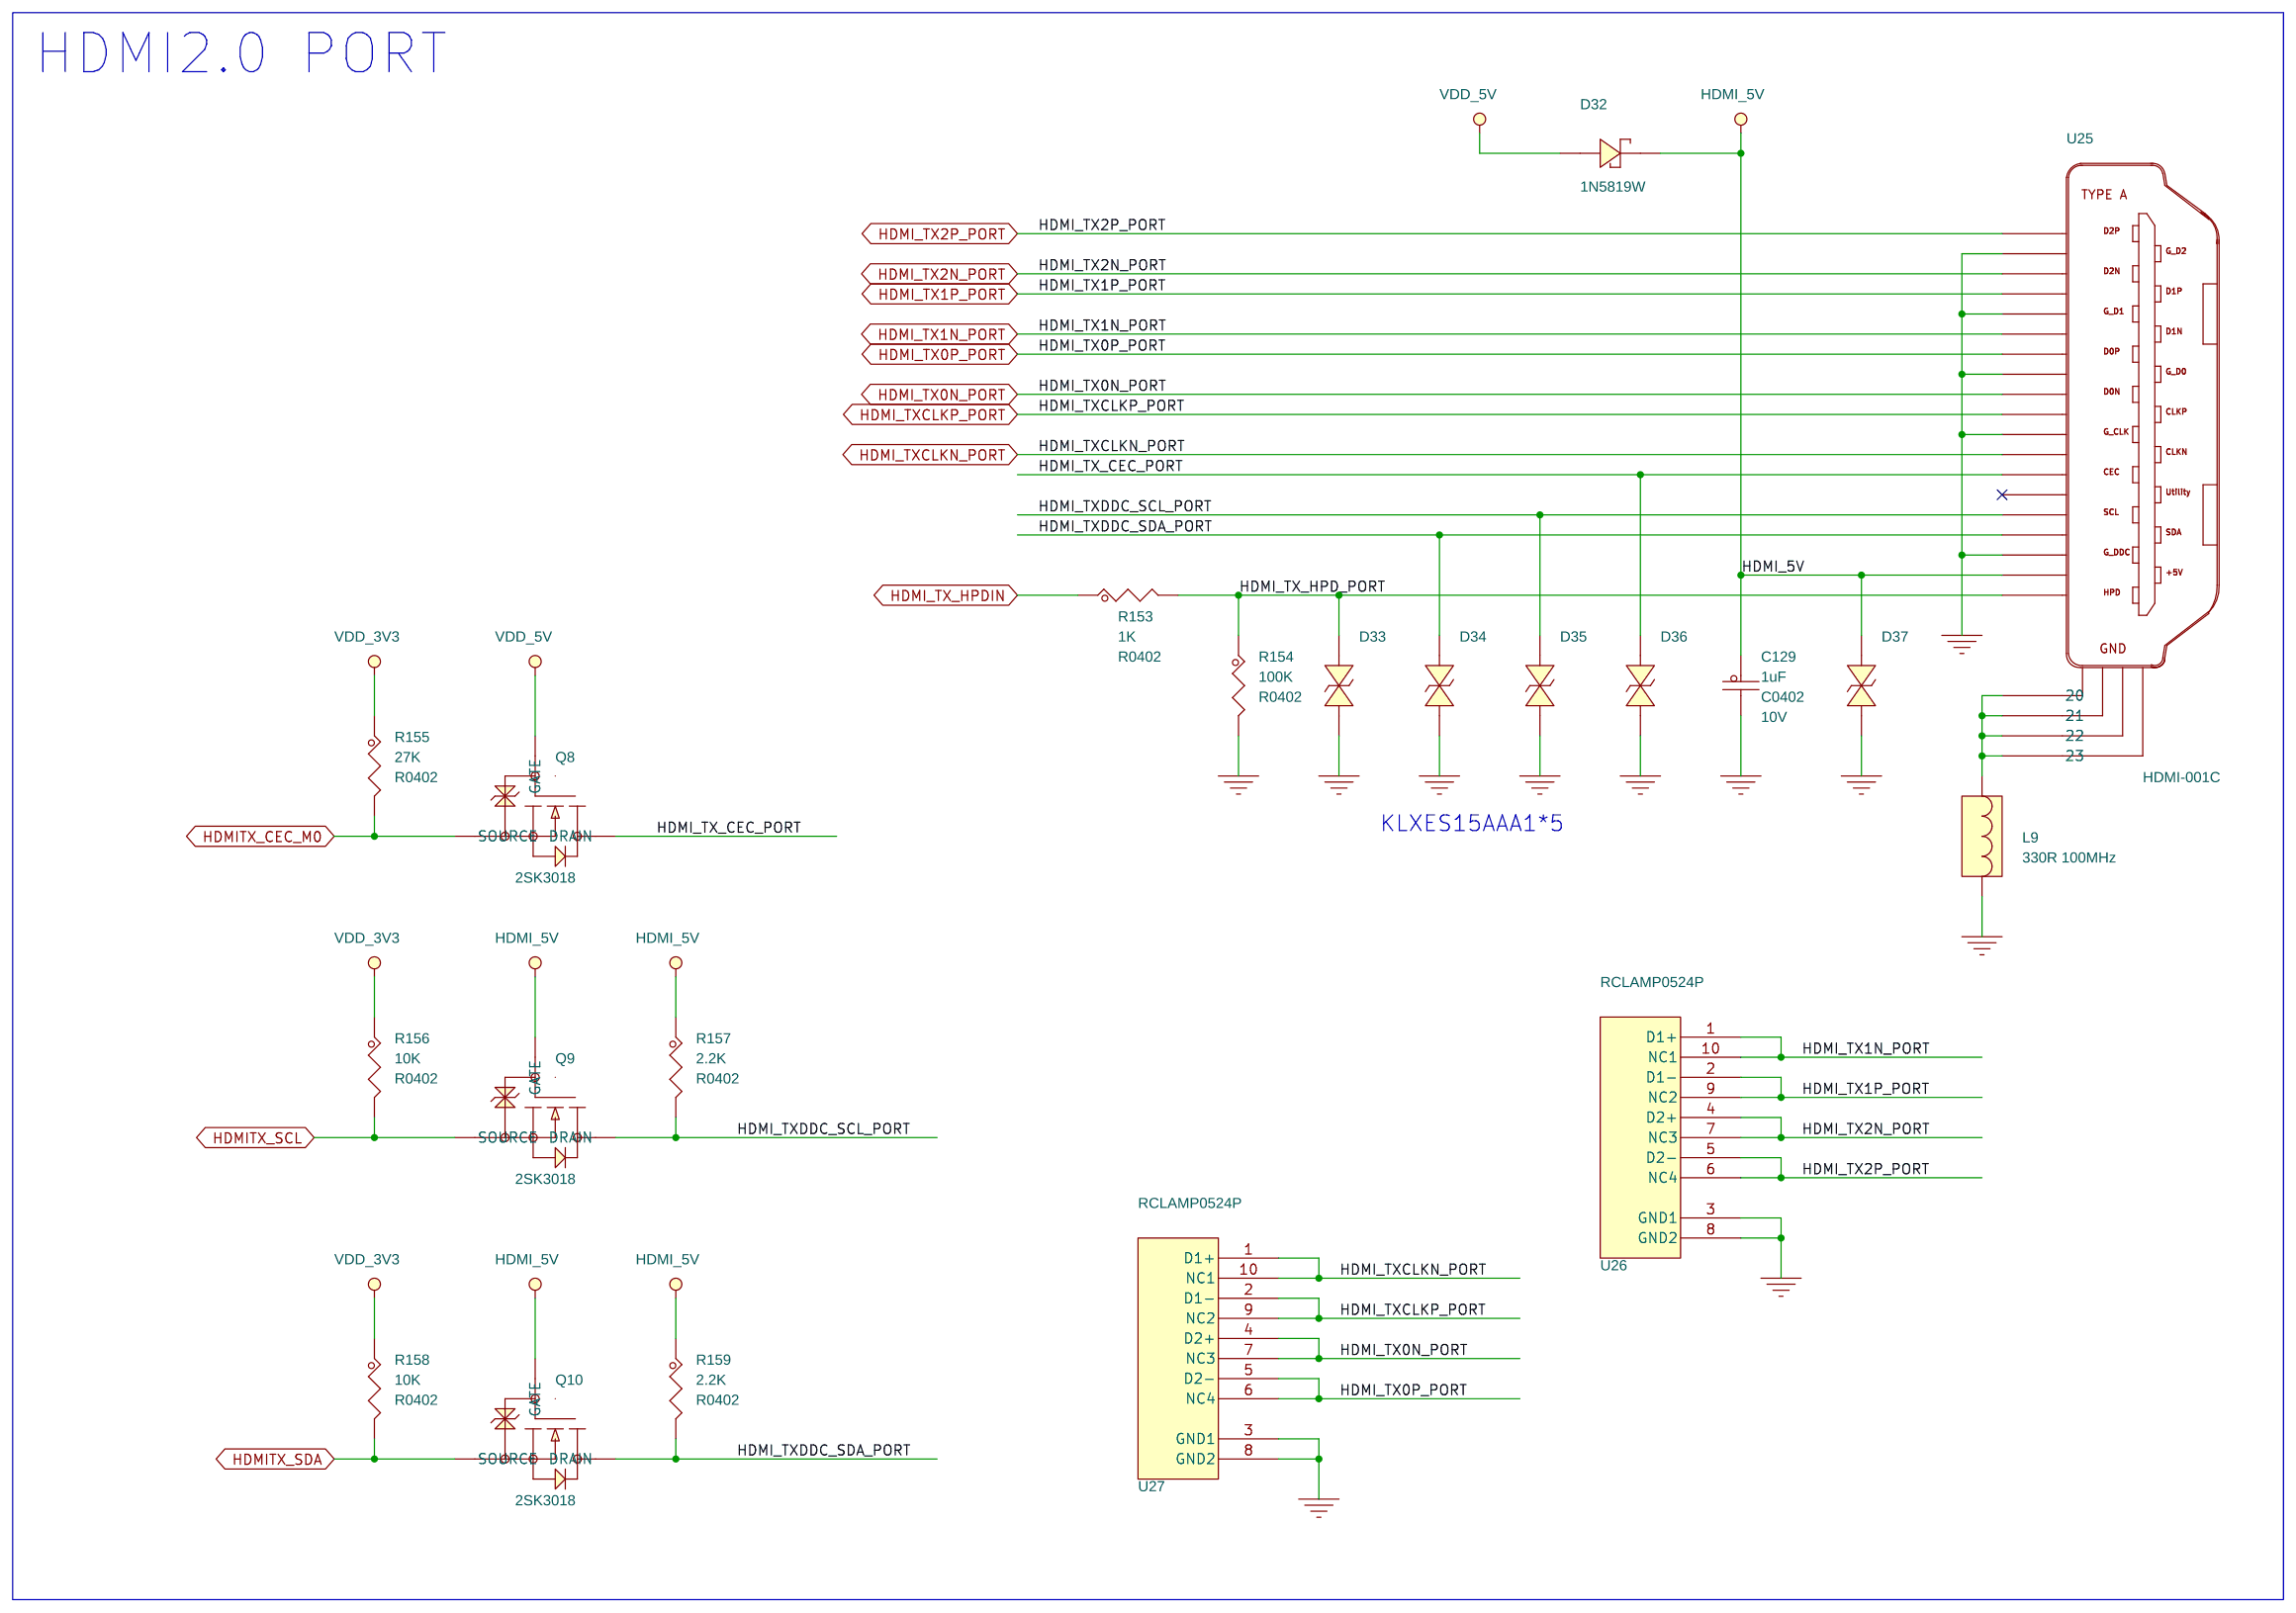
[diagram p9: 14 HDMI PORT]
11 15 MIPI DSI PORT: size A3; note: MIPI DSI PORT
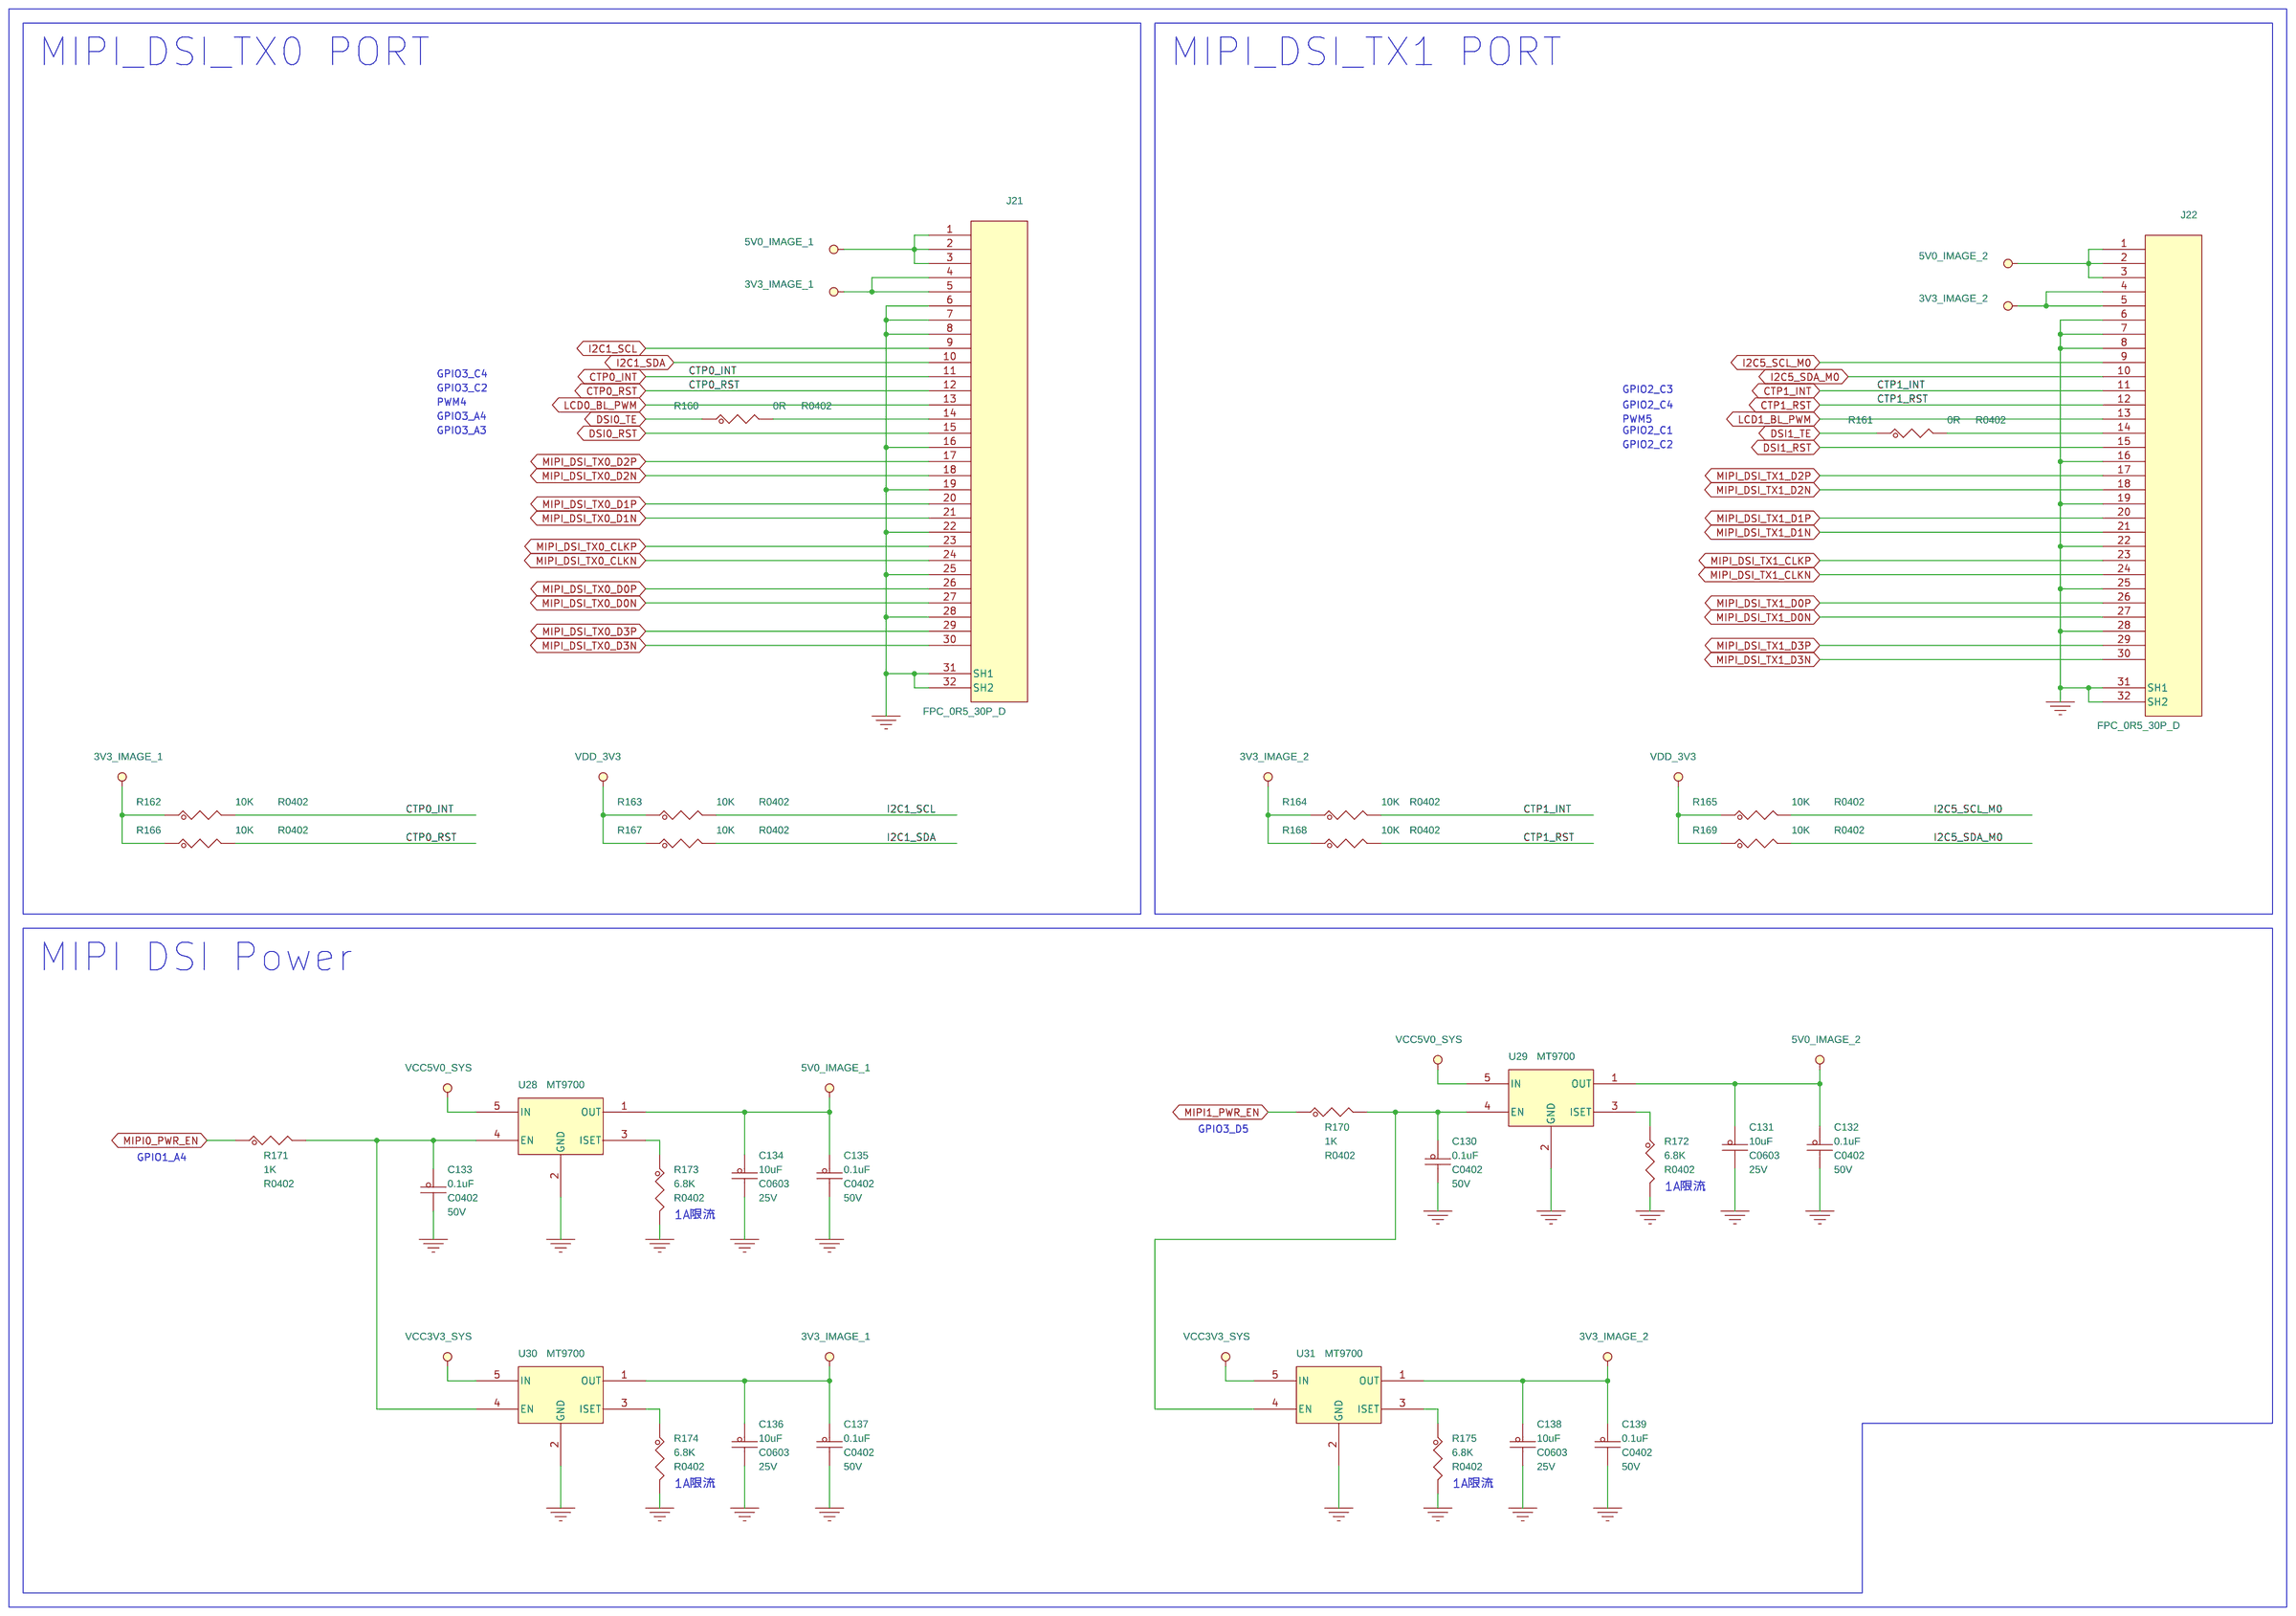
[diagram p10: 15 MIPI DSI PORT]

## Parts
sheet 05 POWER OUT PORT
C38  0.1uF  [C0402]
C39  10uF  [C0603]
C40  0.1uF  [C0402]
C41  0.1uF  [C0402]
C42  10uF  [C0603]
C43  0.1uF  [C0402]
C44  0.1uF  [C0402]
C45  10uF  [C0603]
C46  0.1uF  [C0402]
J3  PH-6A  [PH-1X6-2P0]
Q5  AO3407  [SOT23]
Q6  SS8050  [SOT23]
R26  0R  [R0603]
R27  20K  [R0402]
R28  510R  [R0402]
R29  10K  [R0402]
R30  1K  [R0402]
R31  6.8K  [R0402]
R32  1K  [R0402]
R33  6.8K  [R0402]
U6  MT9700  [SOT23-5]
U7  MT9700  [SOT23-5]
sheet 06 BTB Connector
C47  0.1uF  [C0402]
C48  0.1uF  [C0402]
C49  0.1uF  [C0402]
C50  0.1uF  [C0402]
C51  0.1uF  [C0402]
C52  0.1uF  [C0402]
C53  1uF  [C0402]
J4  SGDBM-05-80P-H10  [SGDBM-05-80P-H10]
J5  SGDBF-05-80P-H30  [SGDBF-05-80P-H30]
J6  SGDBM-05-80P-H10  [SGDBM-05-80P-H10]
J7  SGDBF-05-80P-H30  [SGDBF-05-80P-H30]
R34  15K  [R0402]
R35  10K  [R0402]
SS1  M2.5X4mm  [SMTSO-M2r5]
SS2  M2.5X4mm  [SMTSO-M2r5]
SS3  M2.5X4mm  [SMTSO-M2r5]
SS4  M2.5X4mm  [SMTSO-M2r5]
sheet 09 RS485 PORT
C73  0.1uF  [C0402]
C74  0.1uF  [C0402]
D22  RB521S-30  [SOD523]
D23  RB521S-30  [SOD523]
D24  SMBJ6.5CA  [SMB-CA]
D25  SMBJ6.5CA  [SMB-CA]
D26  SMBJ6.5CA  [SMB-CA]
D27  SMBJ6.5CA  [SMB-CA]
J13  1X2PIN-M  [DIP-1x2-2P54]
J14  1X2PIN-M  [DIP-1x2-2P54]
J15  WJ15EDGRC-3.81-4P  [DB2ERC-3P81-4P]
R67  10K  [R0402]
R68  10K  [R0402]
R69  10K  [R0402]
R70  10K  [R0402]
R71  4.7K  [R0402]
R72  4.7K  [R0402]
R73  120R  [R0603]
R74  120R  [R0603]
R75  10K  [R0402]
R76  4.7K  [R0402]
R77  10K  [R0402]
R78  4.7K  [R0402]
R79  0R  [R0603]
R80  0R  [R0603]
R81  0R  [R0603]
R82  0R  [R0603]
U14  MAX3485  [SOP8]
U15  MAX3485  [SOP8]
sheet 11 ETH
C77  0.1uF  [C0402]
C78  4.7uF  [C0402]
C79  0.1uF  [C0402]
C80  4.7uF  [C0402]
C81  18pF  [C0402]
C82  18pF  [C0402]
C83  0.1uF  [C0402]
C84  0.1uF  [C0402]
C85  4.7uF  [C0402]
C86  0.1uF  [C0402]
C87  0.1uF  [C0402]
C88  0.1uF  [C0402]
C89  4.7uF  [C0402]
C90  0.1uF  [C0402]
C91  0.1uF  [C0402]
C92  0.1uF  [C0402]
C93  4.7uF  [C0402]
C94  0.1uF  [C0402]
C95  0.1uF  [C0402]
C96  4.7uF  [C0402]
C97  0.1uF  [C0402]
C98  0.1uF  [C0402]
C99  0.1uF  [C0402]
C100  4.7uF  [C0402]
C101  4.7uF  [C0402]
C102  0.1uF  [C0402]
C103  0.1uF  [C0402]
D28  RB521S-30  [SOD523]
J17  HY911130A  [HY911130A]
L4  2.2uH  [L2520]
L5  100R 100MHz  [L0603]
L6  100R 100MHz  [L0603]
L7  100R 100MHz  [L0603]
R89  NC  [R0402]
R90  NC  [R0402]
R91  0R  [R0402]
R92  0R  [R0402]
R93  4.7K  [R0402]
R94  4.7K  [R0402]
R95  4.7K  [R0402]
R96  22R  [R0402]
R97  22R  [R0402]
R98  2.49K  [R0402]
R99  22R  [R0402]
R100  22R  [R0402]
R101  22R  [R0402]
R102  22R  [R0402]
R103  4.7K  [R0402]
R104  4.7K  [R0402]
R105  4.7K  [R0402]
R106  NC  [R0402]
R107  0R  [R0402]
R108  4.7K  [R0402]
R109  4.7K  [R0402]
R110  4.7K  [R0402]
R111  NC  [R0402]
R112  0R  [R0402]
R113  NC  [R0402]
R114  510R  [R0402]
R115  510R  [R0402]
R116  4.7K  [R0402]
R117  4.7K  [R0402]
R118  4.7K  [R0402]
R119  NC  [R0402]
R120  10K  [R0402]
R121  0R  [R0402]
R122  NC  [R0402]
R123  0R  [R0402]
R124  0R  [R0402]
U16  JL2101B-N040C  [qfp_40p_r]
Y1  25MHz  [3225]
sheet 12 WLAN BT
C104  10pF  [C0402]
C105  NC  [C0402]
C106  NC  [C0402]
C107  0.1uF  [C0402]
C108  10uF  [C0603]
C109  0.1uF  [C0402]
CN1  WiFi-Ant  [UFL-3]
Q7  AO3407  [SOT23]
R125  2.2R  [R0402]
R126  2.2R  [R0402]
R127  10K  [R0402]
R128  510R  [R0402]
U17  TL8821CUB  [RL-UM02WBS-8723BU]
sheet 13 USB PORT
C110  1uF  [C0402]
C111  1uF  [C0402]
C112  0.1uF  [C0402]
C113  0.1uF  [C0402]
C114  10uF  [C0402]
C115  0.1uF  [C0402]
C116  0.1uF  [C0402]
C117  NC  [C0402]
C118  NC  [C0402]
C119  0.1uF  [C0402]
C120  10uF  [C0402]
C121  0.1uF  [C0402]
C122  0.1uF  [C0402]
C123  10uF  [C0402]
C124  0.1uF  [C0402]
C125  0.1uF  [C0402]
C126  4.7uF  [C0402]
C127  0.1uF  [C0402]
C128  0.1uF  [C0402]
D29  BAT54A  [SOT23]
D30  KLXES15AAA1  [ES0402]
D31  KLXES15AAA1  [ES0402]
J18  USB3D0_USB2D0-A-D  [USB3D0-AF-18P]  (sections A,B)
J19  TYPE-C  [TYPE-C-31-M-12]
J20  USB-A-D  [USB-A-D]  (sections A,B)
L8  120R 100MHz  [L0603]
R129  2.2R  [R0402]
R130  2.2R  [R0402]
R131  2.2R  [R0402]
R132  2.2R  [R0402]
R133  2.2R  [R0402]
R134  2.2R  [R0402]
R135  100R  [R0402]
R136  2.2R  [R0402]
R137  2.2R  [R0402]
R138  2.2R  [R0402]
R139  2.2R  [R0402]
R140  1K  [R0402]
R141  2.2R  [R0402]
R142  2.2R  [R0402]
R143  3.4K  [R0402]
R144  100K  [R0402]
R145  100K  [R0402]
R146  1K  [R0402]
R147  3.4K  [R0402]
R148  10K  [R0402]
R149  1K  [R0402]
R150  15K  [R0402]
R151  0R  [R0603]
R152  6.8K  [R0402]
U18  RCLAMP0524P  [USON_10]
U19  RCLAMP0524P  [USON_10]
U20  RCLAMP0524P  [USON_10]
U21  MT9700  [SOT23-5]
U22  CH334F  [QFN24]
U23  MT9700  [SOT23-5]
U24  MT9700  [SOT23-5]
Y2  12MHz  [3225]
sheet 14 HDMI PORT
C129  1uF  [C0402]
D32  1N5819W  [SOD-123]
D33  KLXES15AAA1  [ES0402]
D34  KLXES15AAA1  [ES0402]
D35  KLXES15AAA1  [ES0402]
D36  KLXES15AAA1  [ES0402]
D37  KLXES15AAA1  [ES0402]
L9  330R 100MHz  [L0603]
Q8  2SK3018  [SOT23]
Q9  2SK3018  [SOT23]
Q10  2SK3018  [SOT23]
R153  1K  [R0402]
R154  100K  [R0402]
R155  27K  [R0402]
R156  10K  [R0402]
R157  2.2K  [R0402]
R158  10K  [R0402]
R159  2.2K  [R0402]
U25  HDMI-001C  [HDMI-SMD]
U26  RCLAMP0524P  [USON_10]
U27  RCLAMP0524P  [USON_10]
sheet 15 MIPI DSI PORT
C130  0.1uF  [C0402]
C131  10uF  [C0603]
C132  0.1uF  [C0402]
C133  0.1uF  [C0402]
C134  10uF  [C0603]
C135  0.1uF  [C0402]
C136  10uF  [C0603]
C137  0.1uF  [C0402]
C138  10uF  [C0603]
C139  0.1uF  [C0402]
J21  FPC_0R5_30P_D  [FPC-30P-0P5]
J22  FPC_0R5_30P_D  [FPC-30P-0P5]
R160  0R  [R0402]
R161  0R  [R0402]
R162  10K  [R0402]
R163  10K  [R0402]
R164  10K  [R0402]
R165  10K  [R0402]
R166  10K  [R0402]
R167  10K  [R0402]
R168  10K  [R0402]
R169  10K  [R0402]
R170  1K  [R0402]
R171  1K  [R0402]
R172  6.8K  [R0402]
R173  6.8K  [R0402]
R174  6.8K  [R0402]
R175  6.8K  [R0402]
U28  MT9700  [SOT23-5]
U29  MT9700  [SOT23-5]
U30  MT9700  [SOT23-5]
U31  MT9700  [SOT23-5]

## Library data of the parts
C38 C40 C41 C43 C44 C46 C73 C74 C77 C79 C83 C84 C86-C88 C90-C92 C94 C95 C97-C99 C102 C103 C112 C113 C115 C116 C119 C121 C122 C124 C125 C127 C128 C130 C132 C133 C135 C137 C139 = CAP_NP: Voltage: 50V; 规格: 贴片电容0.1uF 10% 50V X5R 0402; 规格编号: 0402X104K500NT; 规格书: 风华电容.pdf; 价格: 0.029826; 类别: 贴片电容0402; 品牌: 风华; 生命周期: 量产; 条码: EBF29060118
C39 C42 C45 C131 C134 C136 C138 = CAP_NP: Voltage: 25V; 规格: 贴片电容10uF 20% 25V X5R 0603; 规格编号: CL10A106MA8NRNC; 规格书: 三星电容.pdf; 价格: 0.109811; 类别: 贴片电容0603; 品牌: 三星; 生命周期: 量产; 条码: EBF29060171
J3 = 1X6PIN: 规格: 直针PH2.0-6P 间距2.0MM 拔插式 接插件; 规格书: 博穆精密_PH2.0-A.pdf; 价格: 0.0228; 可替代料: EBF29020026; 类别: PH连接器; 品牌: 博穆精密; 生命周期: 量产; 条码: EBF29020026
Q5 Q7 = MOSFET_P: 规格: P沟道MOS 导通电阻60mΩ 电流4.1A 3V可驱动; 规格书: 合科泰-AO3407.pdf; 价格: 0.199827; 类别: P-MOS; 品牌: 合科泰; 生命周期: 量产; 丝印: A7; 条码: EBF29280012
Q6 = NPN: 规格: 贴片三极管SS8050 集电极电流1.5A 额定功率300mW NPN; 规格书: 江苏长电-SS8050Y1.pdf; 价格: 0.086744; 类别: 贴片三极管SOT-23; 品牌: 江苏长电; 生命周期: 量产; 丝印: Y1; 条码: EBF29090001
R26 R79-R82 R151 = RES: 规格: 贴片电阻0R 1% 1/10W 0603; 规格编号: RI0603L0000FT; 规格书: 合科泰-RI系列电阻.pdf; 类别: 贴片电阻0603; 品牌: 合科泰; 生命周期: 量产; 条码: EBF29070063
R27 = RES: 规格: 贴片电阻20K 1% 1/16W 0402; 规格编号: 0402WGF2002TCE; 规格书: 厚声-无铅厚膜电阻.pdf; 价格: 0.002473; 类别: 贴片电阻0402; 品牌: 厚声; 生命周期: 量产; 条码: EBF29070223
R28 R114 R115 R128 = RES: 规格: 贴片电阻510R 1% 1/16W 0402; 规格编号: 0402WGF5100TCE; 规格书: 厚声-无铅厚膜电阻.pdf; 价格: 0.003791; 类别: 贴片电阻0402; 品牌: 厚声; 生命周期: 量产; 条码: EBF29070293
R29 R35 R67-R70 R75 R77 R120 R127 R148 R156 R158 R162-R169 = RES: 规格: 贴片电阻10K 1% 1/16W 0402; 规格编号: 0402WGF1002TCE; 规格书: 厚声-无铅厚膜电阻.pdf; 价格: 0.002773; 类别: 贴片电阻0402; 品牌: 厚声; 生命周期: 量产; 条码: EBF29070046
R30 R32 R140 R146 R149 R153 R170 R171 = RES: 规格: 贴片电阻1K 1% 1/16W 0402; 规格编号: RI0402L1001FT; 规格书: 合科泰-RI系列电阻.pdf; 类别: 贴片电阻0402; 品牌: 合科泰; 生命周期: 量产; 条码: EBF29070050
R31 R33 R152 R172-R175 = RES: 规格: 贴片电阻6.8K 1% 1/16W 0402; 规格编号: RI0402L6801FT; 规格书: 合科泰-RI系列电阻.pdf; 类别: 贴片电阻0402; 品牌: 合科泰; 生命周期: 量产; 条码: EBF29070052
U6 U7 U21 U23 U24 U28-U31 = MT9700: 规格: 负载开关 工作电压2.4V-5.5V 最大电流2A 过流保护; 规格书: MT9700.pdf; 价格: 0.483492; 类别: 功率开关; 品牌: 西安航天民芯; 生命周期: 量产; 丝印: D00HA-X; 条码: EBF29280004
C47-C52 C107 C109 = CAP_NP: voltage: 50V; 规格: 贴片电容0.1uF 10% 50V X5R 0402; 规格编号: 0402X104K500NT; 规格书: 风华电容.pdf; 价格: 0.029826; 类别: 贴片电容0402; 品牌: 风华; 生命周期: 量产; 条码: EBF29060118
C53 C110 C111 C129 = CAP_NP: Voltage: 10V; 规格: 贴片电容1uF 10% 10V X5R 0402; 规格编号: 0402X105K100NT; 规格书: 风华电容.pdf; 价格: 0.01191; 类别: 贴片电容0402; 品牌: 风华; 生命周期: 量产; 条码: EBF29060121
J4 J6 = SGDBM-05-80P-H10: 规格: 0.5mm BTB公座2*40P 双槽 立贴式 合高4.0mm; 规格书: 山谷道_双槽板对板公母立贴式0_5mm.pdf; 类别: BTB连接器; 品牌: 山谷道; 生命周期: 量产; 条码: EBFCIS221220164941
J5 J7 = SGDBM-05-80P-H10: 规格: 0.5mm BTB母座2*40P 双槽 立贴式 合高4.0mm; 规格书: 山谷道_双槽板对板公母立贴式0_5mm.pdf; 类别: BTB连接器; 品牌: 山谷道; 生命周期: 量产; 条码: EBFCIS221220165510
R34 R150 = RES: 规格: 贴片电阻15K 1% 1/16W 0402; 规格编号: RI0402L1502FT; 规格书: 合科泰-RI系列电阻.pdf; 类别: 贴片电阻0402; 品牌: 合科泰; 生命周期: 量产; 条码: EBF29070222
SS1-SS4 = SPACER: 备注: BTB核心板固定铜柱; 规格: SMT贴片螺母M2.5 台阶高度1.4MM 台阶外径：4.5MM 螺柱长度：4MM; 规格编号: SMTSO2540CTJ; 规格书: 雄和远景_SMTSO2530CTJ.pdf; 类别: 贴片螺母; 品牌: 雄和远景; 生命周期: 量产; 条码: EBFCIS230525101139
D22 D23 D28 = DIODE_SCHTKY: 规格: 直流反向耐压(Vr)：30V 平均整流电流(Io)：200mA 正向压降(Vf)：500mV@200mA 30V@100mA,VF=350mV@10mA; 规格书: 江苏长电_RB521S-30.pdf; 价格: 0.06781; 类别: 贴片肖特基二极管; 品牌: 江苏长电; 生命周期: 量产; 条码: EBFCIS221114153437
D24-D27 = DIODE_BI-DIR_TRIG: 规格: TVS二极管 箝位电压11.2V 击穿电压7.22V 反向关断电压6.5V; 规格书: 君耀电子-SMBJ15CA.pdf; 价格: 0.226009; 类别: 贴片TVS; 品牌: 君耀电子; 生命周期: 量产; 条码: EBF29140023
J13 J14 = B2S: 规格: 排针 总PIN数2 间距2.54mm 直插; 规格书: 州日_单排针_直插_2P54.pdf; 类别: 直插单排排针; 生命周期: 量产; 条码: EBF29020034
J15 = CON4: 规格: 插拔式接线端子 间距3.81mm 90度弯针 4PIN; 规格书: 康奈克斯电气-绿色端子弯针插座.pdf; 价格: 0.198381; 类别: 绿色插拔式接线端子; 品牌: 康奈克斯电气; 生命周期: 量产; 条码: EBF29040009
R71 R72 R76 R78 R93-R95 R103-R105 R108-R110 R116-R118 = RES: 规格: 贴片电阻4.7K 1% 1/16W 0402; 规格编号: RI0402L4701FT; 规格书: 合科泰-RI系列电阻.pdf; 类别: 贴片电阻0402; 品牌: 合科泰; 生命周期: 量产; 条码: EBF29070047
R73 R74 = RES: 规格: 贴片电阻120R 1% 1/10W 0603; 规格编号: RI0603L1200FT; 规格书: 合科泰-RI系列电阻.pdf; 类别: 贴片电阻0603; 品牌: 合科泰; 生命周期: 量产; 条码: EBF29070067
U14 U15 = TJA1057GT3: 规格: RS-485/RS-422芯片 收发器 允许32个器件连接总线 协议类别RS-485 电源电压3.3V 数据速率10Mbps; 规格编号: MAX3485ED; 规格书: HTC_MAX3485ED.pdf; 价格: 1.31; 类别: RS485/RS422芯片; 品牌: HTC; 生命周期: 量产; 条码: EBF29150034
C78 C80 C85 C89 C93 C96 C100 C101 C126 = CAP_NP: Voltage: 10V; 规格: 贴片电容4.7uF 10% 10V X5R 0402; 规格编号: CC0402KRX5R6BB475; 规格书: 国巨-贴片电容.pdf; 价格: 0.059058; 类别: 贴片电容0402; 品牌: 国巨; 生命周期: 量产; 条码: EBF29060248
C81 C82 = CAP_NP: Voltage: 50V; 规格: 贴片电容18pF 5% 50V C0G 0402; 规格编号: 0402CG180J500NT; 规格书: 风华电容.pdf; 价格: 0.00515; 类别: 贴片电容0402; 品牌: 风华; 生命周期: 量产; 条码: EBF29060235
J17 = HY911130A: 规格: 屏蔽式以太网连接器RJ45 引脚数14 LED灯黄绿 1000M; 规格书: 汉仁_1000M_ HY911130A.pdf; 价格: 11.12; 可替代料: EBF29040053; 类别: 网口; 品牌: 汉仁; 生命周期: 量产; 条码: EBF29040053
L4 = IND: 规格: 功率电感2.2uH 2.2uH ±20% 2.06A 85mΩ; 规格编号: WIP252012P-2R2ML; 规格书: 佳邦_ WIP252012P-2R2ML.pdf; 价格: 0.129914; 类别: 贴片电感2520; 品牌: 佳邦; 生命周期: 量产; 条码: EBFCIS220927171910
L5-L7 = BEAD: 规格: 磁珠100Ω @100MHz 额定电流3A 直流电阻30mΩ; 规格编号: UPZ1608E101-3R0TF; 规格书: 顺络-磁珠.pdf; 价格: 0.021567; 类别: 贴片磁珠0603; 品牌: 顺络; 生命周期: 量产; 条码: EBF29050038
R89 R90 R106 R111 R113 R119 R122 = RES: 规格: 贴片电阻NC 预留; 类别: 贴片电阻0402; 条码: EBF29070087
R91 R92 R107 R112 R121 R123 R124 R160 R161 = RES: 规格: 贴片电阻0R 1% 1/16W 0402; 规格编号: RI0402L000FT; 规格书: 合科泰-RI系列电阻.pdf; 类别: 贴片电阻0402; 品牌: 合科泰; 生命周期: 量产; 条码: EBF29070049
R96 R97 R99-R102 = RES: 规格: 贴片电阻22R 1% 1/16W 0402; 规格编号: RI0402L22R0FT; 规格书: 合科泰-RI系列电阻.pdf; 类别: 贴片电阻0402; 品牌: 合科泰; 生命周期: 量产; 条码: EBF29070181
R98 = RES: 规格: 贴片电阻2.49K 1% 1/16W 0402; 规格编号: 0402WGF2491TCE; 规格书: 厚声-无铅厚膜电阻.pdf; 价格: 0.004709; 类别: 贴片电阻0402; 品牌: 厚声; 生命周期: 量产; 条码: EBF29070292
U16 = RTL8211F: 备注: 旧版芯片的优化升级版本 Pin to Pin芯片; 规格: 以太网芯片 10M/100M/1000M 控制接口：RGMII RGMII电压：3.3V/2.5V/1.8V/1.5V; 规格书: 景略半导体-JL2101-v1.07.pdf; 类别: 以太网芯片; 品牌: 景略半导体; 生命周期: 量产; 条码: EBFCIS230802110114
Y1 = CRYSTAL_4P: 规格: 无源晶振25MHZ 50Ω 16pF 3225; 规格编号: X322525MQB4SI; 规格书: 扬兴科技-25MHZ.pdf; 价格: 0.385846; 类别: 贴片晶振 3225; 品牌: 扬兴科技; 生命周期: 量产; 条码: EBF29100005
C104 = CAP_NP: voltage: 50V; 规格: 贴片电容10pF 5% 50V C0G 0402; 规格编号: 0402CG100J500NT; 规格书: 风华电容.pdf; 价格: 0.00453; 类别: 贴片电容0402; 品牌: 风华; 生命周期: 量产; 条码: EBF29060127
C105 C106 C117 C118 = CAP_NP: 规格: 贴片电容NC 预留; 类别: 贴片电容0402; 条码: EBF29060149
C108 = CAP_NP: voltage: 25V; 规格: 贴片电容10uF 20% 25V X5R 0603; 规格编号: CL10A106MA8NRNC; 规格书: 三星电容.pdf; 价格: 0.109811; 类别: 贴片电容0603; 品牌: 三星; 生命周期: 量产; 条码: EBF29060171
CN1 = WIFI_ANT: 规格: RF同轴连接器（天线座）; 规格编号: KH-IPEX-K501-29; 规格书: 金航标-天线座.pdf; 价格: 0.247224; 类别: WiFi天线座; 品牌: 金航标; 生命周期: 量产; 条码: EBF430005
R125 R126 R129-R134 R136-R139 R141 R142 = RES: 规格: 贴片电阻2.2R 1% 1/16W 0402; 规格编号: 0402WGF220KTCE; 规格书: 厚声-无铅厚膜电阻.pdf; 价格: 0.003072; 类别: 贴片电阻0402; 品牌: 厚声; 生命周期: 量产; 条码: EBF29070280
U17 = RTL8723: 规格: RTL8821 WiFi模块 接口类型：usb 工作电压：3.3V 传输速率：150M+433M 工作频率：2.4G+5.8G 无线标准：802.11AC/B/G/n 有效通信距离：100m; 价格: 17; 类别: WiFi模块; 品牌: 创凌; 生命周期: 量产; 条码: EBF29250002
C114 C120 C123 = CAP_NP: Voltage: 10V; 规格: 贴片电容10uF 20% 10V X5R 0402; 规格编号: CL05A106MP8NUB8; 规格书: 三星电容.pdf; 价格: 0.518415; 类别: 贴片电容0402; 品牌: 三星; 生命周期: 量产; 条码: EBF29060247
D29 = BAT54A: 规格: 肖特基二极管 直流反向耐压30V 平均整流电流200mA 正向压降1V@100mA SOT-23; 规格书: 晶导微电子-BAT54S.pdf; 价格: 0.054466; 类别: 贴片肖特基二极管; 品牌: 晶导微电子; 生命周期: 量产; 条码: EBF29140065
D30 D31 D33-D37 = DIODE_BI-DIR_TRIG: 规格: 用于 USB3.0、HDMI 0.5pF、5V、±15kV ESD 保护二极管; 规格书: KLXES15AAA1.pdf; 价格: 0.09719; 类别: 贴片ESD; 品牌: 永裕泰; 生命周期: 量产; 条码: EBF29140063
J18 = USB3D0_USB2D0-A-D: 规格: USB3.0_USB2.0母座; 规格编号: UEA1112C-UHS6-4F; 规格书: UEA1112C-UHS6-4F.pdf; 类别: USB接口; 品牌: 富士康; 生命周期: 量产; 条码: EBF29040092
J19 = TYPE-C-31-M-12: 规格: Type-C母座 16P 贴片 USB-2.0 插座 高清传输接口 4固定插脚 双向; 规格书: TYPE-C-31-M-12母座贴片.pdf; 价格: 1.06; 类别: USB接口; 品牌: 韩国韩容; 生命周期: 量产; 条码: EBF29040004
J20 = USB-A-D: 规格: 双层USB接口 A型接口 90度双排弯插脚 AF母座 焊接式; 规格编号: 907-111A1012D10200; 规格书: 精拓金-双层USB.pdf; 价格: 0.22; 类别: USB接口; 品牌: 精拓金; 生命周期: 量产; 条码: EBF29020027
L8 = BEAD: 规格: 磁珠120Ω @100MHz 额定电流300mA 直流电阻200mΩ; 规格编号: GZ1608D121TF; 规格书: 顺络-磁珠120Ω±25%100MHZ.pdf; 价格: 0.024822; 类别: 贴片磁珠0603; 品牌: 顺络; 生命周期: 量产; 条码: EBF29050009
R135 = RES: 规格: 贴片电阻100R 1% 1/16W 0402; 规格编号: RI0402L1000FT; 规格书: 合科泰-RI系列电阻.pdf; 类别: 贴片电阻0402; 品牌: 合科泰; 生命周期: 量产; 条码: EBF29070053
R143 R147 = RES: 规格: 贴片电阻3.4K 1% 1/16W 0402; 规格编号: RI0402L3401FT; 规格书: 合科泰-RI系列电阻.pdf; 类别: 贴片电阻0402; 品牌: 合科泰; 生命周期: 量产; 条码: EBF29070186
R144 R145 R154 = RES: 规格: 贴片电阻100K 1% 1/16W 0402; 规格编号: RI0402L1003FT; 规格书: 合科泰-RI系列电阻.pdf; 类别: 贴片电阻0402; 品牌: 合科泰; 生命周期: 量产; 条码: EBF29070054
U18-U20 U26 U27 = RCLAMP0524P: 规格: TVS二极管 箝位电压17V 击穿电压8V 反向关断电压5V; 规格书: 台舟-RCLAMP0524P.pdf; 价格: 0.185957; 类别: 贴片TVS; 品牌: 台舟; 生命周期: 量产; 条码: EBF29140046
U22 = CH334F: 规格: USB HUB芯片 工作电压3.3V 5V 协议类别USB2.0 支持高速(480Mbps) 全速(12Mbps)和低速(1.5Mbps)模式; 规格书: 南京沁恒_CH334F.pdf; 价格: 2.09; 类别: USB芯片; 品牌: 南京沁恒; 生命周期: 量产; 条码: EBFCIS221222095807
Y2 = CRYSTAL_4P: 规格: 无源晶振12MHZ 80Ω 20pF 3225; 规格编号: X322512MSB4SI; 规格书: 扬兴科技-贴片晶振.pdf; 价格: 0.327763; 可替代料: EBF29100013; 类别: 贴片晶振 3225; 品牌: 扬兴科技; 生命周期: 量产; 条码: EBF29100013
D32 = DIODE_SCHTKY: 规格: 肖特基二极管 直流反向耐压40V 平均整流电流1A 正向压降0.6V@1A SOD-123; 规格书: 1N5819W.pdf; 价格: 0.175675; 类别: 贴片肖特基二极管; 品牌: 台湾迪嘉; 生命周期: 量产; 丝印: SL; 条码: EBF29140016
L9 = BEAD: 规格: 磁珠330Ω @100MHz 额定电流1.7A 直流电阻80mΩ; 规格编号: MPZ1608S331ATA00; 规格书: TDK-MPZ1608S331ATA00.pdf; 类别: 贴片磁珠0603; 品牌: TDK; 生命周期: 量产; 条码: EBF29050003
Q8-Q10 = 2SK3018: 规格: N沟道MOS 导通电阻8Ω 电流10mA 0.8V可驱动; 规格书: 长电科技-2SK3018.pdf; 价格: 0.120725; 类别: N-MOS; 品牌: 江苏长电; 生命周期: 量产; 丝印: KN; 条码: EBF29280009
R155 = RES: 规格: 贴片电阻27K 1% 1/16W 0402; 规格编号: AC0402FR-0727KL; 规格书: YAGEO国巨厚膜无铅电阻.pdf; 价格: 0.007054; 类别: 贴片电阻0402; 品牌: 国巨; 生命周期: 量产; 条码: EBF29070003
R157 R159 = RES: 规格: 贴片电阻2.2K 1% 1/16W 0402; 规格编号: RI0402L2201FT; 规格书: 合科泰-RI系列电阻.pdf; 类别: 贴片电阻0402; 品牌: 合科泰; 生命周期: 量产; 条码: EBF29070051
U25 = HDMI-001C: 规格: HDMI立式; 规格书: HDMI-001C.pdf; 类别: HDMI连接器; 品牌: 讯普; 生命周期: 量产; 条码: EBF29040081
J21 J22 = FPC-30P: 规格: FPC连接器 针脚数30 间距0.5mm 高度2.0mm 下接 卧贴 翻盖式; 规格编号: FPC-05F-30PH20; 规格书: FPC-05F-NPH20.pdf; 类别: FPC连接器; 品牌: 讯普; 生命周期: 量产; 条码: EBF29040079

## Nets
1V05_AVDD_PHY: C97.1 C98.1 C99.1 C100.1 R124.2 U16.3(AVDD10_2) U16.8(AVDD10_1) U16.38(AVDD10)
1V05_DVDD_PHY: C93.1 C94.1 C95.1 C96.1 R123.1 U16.21(DVDD10)
1V05_PHY: C79.1 C80.1 L4.2 R123.2 R124.1
1V8_DVDD_PHY: C101.1 C102.1 L7.1 R89.2 R90.1 R106.1 R119.1
3V3_AVDD_PHY: C89.1 C90.1 C91.1 L6.1 U16.11(AVDD33_1) U16.40(AVDD33)
3V3_DVDD_PHY: C85.1 C86.1 C87.1 L5.1 R91.2 R92.2 R107.2 R110.1 R118.2 R120.1 R122.2 U16.29(DVDD33)
3V3_IMAGE_1: C136.1 C137.1 J21.4 J21.5 R162.1 R166.1 U30.1(OUT)
3V3_IMAGE_2: C138.1 C139.1 J22.4 J22.5 R164.1 R168.1 U31.1(OUT)
3V3_OUT: C42.1 C43.1 J3.5 U6.1(OUT)
3V3_WLAN: C108.1 C109.1 Q7.3(DRAIN) U17.8(VCC3V3)
5V0_IMAGE_1: C134.1 C135.1 J21.1 J21.2 J21.3 U28.1(OUT)
5V0_IMAGE_2: C131.1 C132.1 J22.1 J22.2 J22.3 U29.1(OUT)
5V_OUT: C45.1 C46.1 J3.3 U7.1(OUT)
12V_OUT: C39.1 C40.1 J3.1 Q5.3(DRAIN)
GND: C39.2 C40.2 C41.2 C42.2 C43.2 C44.2 C45.2 C46.2 C47.2 C48.2 C49.2 C50.2 C51.2 C52.2 C53.2 C73.2 C74.2 C77.2 C78.2 C79.2 C80.2 C81.2 C82.2 C83.2 C84.2 C85.2 C86.2 C87.2 C88.2 C89.2 C90.2 C91.2 C92.2 C93.2 C94.2 C95.2 C96.2 C97.2 C98.2 C99.2 C100.2 C101.2 C102.2 C103.2 C105.2 C106.2 C108.2 C109.2 C110.2 C111.2 C114.2 C115.2 C116.2 C117.2 C118.1 C119.2 C120.2 C121.2 C122.2 C123.2 C124.2 C125.2 C126.2 C127.2 C128.2 C129.2 C130.2 C131.2 C132.2 C133.2 C134.2 C135.2 C136.2 C137.2 C138.2 C139.2 CN1.2 CN1.3 D24.1 D25.1 D26.1 D27.1 D30.1 D31.1 D33.1 D34.1 D35.1 D36.1 D37.1 J3.2 J3.4 J3.6 J4.7 J4.8 J4.9 J4.10 J4.16 J4.20 J4.23 J4.26 J4.31 J4.32 J4.40 J4.49 J4.50 J4.56 J4.66 J4.67 J4.73 J4.76 J5.1 J5.2 J5.3 J5.13 J5.18 J5.23 J5.24 J5.26 J5.29 J5.36 J5.39 J5.49 J5.54 J5.55 J5.65 J5.66 J5.79 J5.80 J6.1 J6.2 J6.8 J6.11 J6.14 J6.27 J6.30 J6.40 J6.41 J6.55 J6.58 J6.64 J6.68 J6.69 J6.75 J6.79 J7.1 J7.2 J7.12 J7.23 J7.26 J7.33 J7.40 J7.54 J7.58 J7.64 J7.69 J7.70 J7.71 J7.73 J7.75 J7.76 J7.77 J7.78 J7.79 J7.80 J17.10(CHS) J17.15(SH) J17.16(SH1) J18.4(GND1) J18.7(GND2) J18.13(GND1) J18.16(NC3) J18.19(SH1) J18.20(SH2) J18.21(SH1) J18.22(SH2) J19.A1(GND1) J19.A12(GND2) J19.B1(GND4) J19.B12(GND3) J20.4(GND) J20.5(SH1) J20.6(SH2) J20.10(GND) J20.11(SH1) J20.12(SH2) J21.6 J21.7 J21.8 J21.16 J21.19 J21.22 J21.25 J21.28 J21.31(SH1) J21.32(SH2) J22.6 J22.7 J22.8 J22.16 J22.19 J22.22 J22.25 J22.28 J22.31(SH1) J22.32(SH2) L8.2 L9.2 Q6.2(EMITTER) R29.2 R31.2 R33.2 R35.2 R75.2 R76.2 R77.2 R78.2 R98.2 R103.2 R104.2 R105.2 R113.2 R114.2 R115.2 R116.2 R121.1 R143.2 R147.2 R150.2 R152.2 R154.2 R172.2 R173.2 R174.2 R175.2 SS1.1(NC) SS2.1(NC) SS3.1(NC) SS4.1(NC) U6.2(GND) U7.2(GND) U14.5(GND) U15.5(GND) U16.41(GND) U17.1(GND) U17.5(GND) U18.3(GND1) U18.8(GND2) U19.3(GND1) U19.8(GND2) U20.3(GND1) U20.8(GND2) U21.2(GND) U22.25(VSS) U23.2(GND) U24.2(GND) U25.2 U25.5 U25.8 U25.11 U25.17 U26.3(GND1) U26.8(GND2) U27.3(GND1) U27.8(GND2) U28.2(GND) U29.2(GND) U30.2(GND) U31.2(GND) Y1.2(GND1) Y1.4(GND2) Y2.2(GND1) Y2.4(GND2) ; also on sheet 12 13 14 15 16 17 18 19
VCC3V3_SD: C51.1 J4.15 J4.17 ; also on sheet 15
VCC3V3_SYS: U6.5(IN) U30.5(IN) U31.5(IN) ; also on sheet 17 18
VCC5V0_SYS: C47.1 C48.1 J4.1 J4.2 J4.3 J4.4 J4.5 J4.6 U28.5(IN) U29.5(IN) ; also on sheet 12 17
VCC5V0_SYS_2: U7.5(IN) U21.5(IN) U23.5(IN) U24.5(IN) ; also on sheet 17
VCC5V0_USB20_HOST: C110.1 C111.1 C114.1 C115.1 J20.1(VBUS) J20.7(VBUS) U21.1(OUT)
VCC5V0_USB30_HOST: C120.1 C121.1 J18.1(VBUS) J18.10(VBUS) U23.1(OUT)
VCC_1V8: C49.1 C103.1 J4.11 J4.13 L7.2 ; also on sheet 19
VCC_12V: C38.1 R26.1 R27.1 ; also on sheet 13 17 18
VCC_RTC: J4.18 ; also on sheet 15
VCCA_1V8: C50.1 J4.12 J4.14 R34.1 ; also on sheet 19
VCCIO_ACODEC: C52.1 J4.19 J4.21 ; also on sheet 14
VDD_3V3: C73.1 C74.1 C88.1 C92.1 C107.1 C125.1 D22.2 D23.2 L5.2 L6.2 Q7.2(SOURCE) R67.1 R68.1 R69.1 R70.1 R127.1 R151.1 R155.1 R156.1 R158.1 R163.1 R165.1 R167.1 R169.1 U14.8(VCC) U15.8(VCC) ; also on sheet 15 16 17 19
VDD_5V: D32.2 Q8.1(GATE) ; also on sheet 17
B_DM1: J18.11(D-) R129.1 U18.5(D2-) U18.6(NC4)
B_DM2: J20.8(D-) R138.1 U20.4(D2+) U20.7(NC3)
B_DM3: J20.2(D-) R131.1 U20.1(D1+) U20.10(NC1)
B_DP1: J18.12(D+) R130.1 U18.4(D2+) U18.7(NC3)
B_DP2: J20.9(D+) R139.1 U20.5(D2-) U20.6(NC4)
B_DP3: J20.3(D+) R132.1 U20.2(D1-) U20.9(NC2)
BD_CH3: C53.1 J6.20 R34.2 R35.1
CAM0_nRST: J7.35 ; also on sheet 12
CAM0_PWDN: J5.56 ; also on sheet 12
CAM0_PWR_EN: J6.78 ; also on sheet 12
CAM1_nRST: J7.41 ; also on sheet 12
CAM1_PWDN: J7.63 ; also on sheet 12
CAM1_PWR_EN: J5.12 ; also on sheet 12
CC1: D29.2 J19.A5(CC1)
CC2: D29.1 J19.B5(CC2)
CTP0_INT: J6.65 J21.11 R162.2
CTP0_RST: J6.61 J21.12 R166.2
CTP1_INT: J7.55 J22.11 R164.2
CTP1_RST: J7.57 J22.12 R168.2
DSI0_RST: J5.60 J21.15
DSI0_TE: J5.58 R160.1
DSI1_RST: J7.53 J22.15
DSI1_TE: J7.51 R161.1
EDP_BL_EN: J4.39 ; also on sheet 18
EDP_BL_PWM: J5.5 ; also on sheet 18
EDP_HPDIN_M0: J6.66 ; also on sheet 18
EDP_PWR_EN: J6.76 ; also on sheet 18
EDP_TP_INT: J7.65 ; also on sheet 18
EDP_TP_RESET: J6.57 ; also on sheet 18
EDP_TX_AUXN: J6.62 ; also on sheet 18
EDP_TX_AUXP: J6.60 ; also on sheet 18
EDP_TX_D0N: J6.44 ; also on sheet 18
EDP_TX_D0P: J6.42 ; also on sheet 18
EDP_TX_D1N: J6.48 ; also on sheet 18
EDP_TX_D1P: J6.46 ; also on sheet 18
EXT_PWR_EN: J4.27 ; also on sheet 17
FSPI_CLK: J6.29 ; also on sheet 19
FSPI_CS0n: J6.31 ; also on sheet 19
FSPI_D0: J6.33 ; also on sheet 19
FSPI_D1: J6.35 ; also on sheet 19
FSPI_D2: J6.37 ; also on sheet 19
FSPI_D3: J6.39 ; also on sheet 19
GMAC1_INT: J5.10 R111.1
GMAC1_MCLKINOUT_M1: J7.56 R112.1 R113.1
GMAC1_MDC_M1: J7.62 R108.2 U16.13(MDC)
GMAC1_MDIO_M1: J7.60 R109.2 U16.14(MDIO)
GMAC1_RSTn: C84.1 D28.1 J5.4
GMAC1_RXCLK_M1: J7.36 R95.2 R101.1
GMAC1_RXD0_M1: J7.34 R93.2 R96.1
GMAC1_RXD1_M1: J7.32 R94.2 R97.1
GMAC1_RXD2_M1: J7.30 R99.1 R103.1
GMAC1_RXD3_M1: J7.28 R100.1 R104.1
GMAC1_RXDV_CRS_M1: J7.38 R102.1 R105.1
GMAC1_TXCLK_M1: J7.44 U16.20(TXC)
GMAC1_TXD0_M1: J7.52 U16.18(TXD0)
GMAC1_TXD1_M1: J7.50 U16.17(TXD1)
GMAC1_TXD2_M1: J7.48 U16.16(TXD2)
GMAC1_TXD3_M1: J7.46 U16.15(TXD3)
GMAC1_TXEN_M1: J7.42 U16.19(TXCTL)
GPIO2_B7: J7.47 ; also on sheet 19
GPIO2_C0: J7.49 ; also on sheet 19
HDMI_5V: C129.1 D32.1 D37.2 Q9.1(GATE) Q10.1(GATE) R157.1 R159.1 U25.18
HDMI_TX0N_PORT: J5.48 U25.9 U27.4(D2+) U27.7(NC3)
HDMI_TX0P_PORT: J5.46 U25.7 U27.5(D2-) U27.6(NC4)
HDMI_TX1N_PORT: J5.44 U25.6 U26.1(D1+) U26.10(NC1)
HDMI_TX1P_PORT: J5.42 U25.4 U26.2(D1-) U26.9(NC2)
HDMI_TX2N_PORT: J5.40 U25.3 U26.4(D2+) U26.7(NC3)
HDMI_TX2P_PORT: J5.38 U25.1 U26.5(D2-) U26.6(NC4)
HDMI_TX_CEC_PORT: D36.2 Q8.3(DRAIN) U25.13
HDMI_TX_HPD_PORT: D33.2 R153.2 R154.1 U25.19
HDMI_TX_HPDIN: J5.34 R153.1
HDMI_TXCLKN_PORT: J5.50 U25.12 U27.1(D1+) U27.10(NC1)
HDMI_TXCLKP_PORT: J5.52 U25.10 U27.2(D1-) U27.9(NC2)
HDMI_TXDDC_SCL_PORT: D35.2 Q9.3(DRAIN) R157.2 U25.15
HDMI_TXDDC_SDA_PORT: D34.2 Q10.3(DRAIN) R159.2 U25.16
HDMITX_CEC_M0: J5.32 Q8.2(SOURCE) R155.2
HDMITX_SCL: J5.30 Q9.2(SOURCE) R156.2
HDMITX_SDA: J5.28 Q10.2(SOURCE) R158.2
HOST1_DM: J18.2(D-) R136.1 U19.4(D2+) U19.7(NC3)
HOST1_DP: J18.3(D+) R137.1 U19.5(D2-) U19.6(NC4)
HP_DET: J6.80 ; also on sheet 14
HP_SNS: J4.36 ; also on sheet 14
HPL_OUT: J4.34 ; also on sheet 14
HPR_OUT: J4.38 ; also on sheet 14
HUB_3V3: C126.1 C127.1 C128.1 R144.1 R145.1 R151.2 U22.1(OVCUR#) U22.20(VDD3V3)
HUB_DM1: R129.2 U22.11(DM1)
HUB_DM2: R138.2 U22.9(DM2)
HUB_DM3: R131.2 U22.7(DM3)
HUB_DM4: U22.5(DM4) ; also on sheet 13
HUB_DP1: R130.2 U22.12(DP1)
HUB_DP2: R139.2 U22.10(DP2)
HUB_DP3: R132.2 U22.8(DP3)
HUB_DP4: U22.6(DP4) ; also on sheet 13
I2C0_SCL_PMIC: J6.3 ; also on sheet 15
I2C0_SDA_PMIC: J6.5 ; also on sheet 15
I2C1_SCL: J6.7 J21.9 R163.2 ; also on sheet 12
I2C1_SDA: J6.9 J21.10 R167.2 ; also on sheet 12
I2C2_SCL_M1: J6.51 ; also on sheet 16
I2C2_SDA_M1: J6.53 ; also on sheet 16
I2C3_SCL_M0: J6.72 ; also on sheet 16
I2C3_SDA_M0: J6.70 ; also on sheet 16
I2C4_SCL_M0: J7.29 ; also on sheet 18
I2C4_SDA_M0: J7.31 ; also on sheet 18
I2C5_SCL_M0: J7.25 J22.9 R165.2 ; also on sheet 12
I2C5_SDA_M0: J7.27 J22.10 R169.2 ; also on sheet 12
LCD0_BL_PWM: J5.9 J21.13
LCD1_BL_PWM: J5.11 J22.13
MDIN0_PHY: J17.3(TD1-) U16.2(MDIN0)
MDIN1_PHY: J17.7(RD1-) U16.5(MDIN1)
MDIN2_PHY: J17.6(TD2-) U16.7(MDIN2)
MDIN3_PHY: J17.9(RD2-) U16.10(MDIN3)
MDIP0_PHY: J17.2(TD1+) U16.1(MDIP0)
MDIP1_PHY: J17.4(RD1+) U16.4(MDIP1)
MDIP2_PHY: J17.5(TD2+) U16.6(MDIP2)
MDIP3_PHY: J17.8(RD2+) U16.9(MDIP3)
MIC_INN: J4.30 ; also on sheet 14
MIC_INP: J4.28 ; also on sheet 14
MINIPCIE_nWDISABLE: J7.61 ; also on sheet 13
MIPI0_PWR_EN: J6.74 R171.1
MIPI1_PWR_EN: J5.16 R170.1
MIPI_CSI_RX_CLK0N: J5.78 ; also on sheet 12
MIPI_CSI_RX_CLK0P: J5.76 ; also on sheet 12
MIPI_CSI_RX_CLK1N: J5.77 ; also on sheet 12
MIPI_CSI_RX_CLK1P: J5.75 ; also on sheet 12
MIPI_CSI_RX_D0N: J5.70 ; also on sheet 12
MIPI_CSI_RX_D0P: J5.68 ; also on sheet 12
MIPI_CSI_RX_D1N: J5.74 ; also on sheet 12
MIPI_CSI_RX_D1P: J5.72 ; also on sheet 12
MIPI_CSI_RX_D2N: J5.69 ; also on sheet 12
MIPI_CSI_RX_D2P: J5.67 ; also on sheet 12
MIPI_CSI_RX_D3N: J5.73 ; also on sheet 12
MIPI_CSI_RX_D3P: J5.71 ; also on sheet 12
MIPI_DSI_TX0_CLKN: J5.53 J21.24
MIPI_DSI_TX0_CLKP: J5.51 J21.23
MIPI_DSI_TX0_D0N: J5.43 J21.27
MIPI_DSI_TX0_D0P: J5.41 J21.26
MIPI_DSI_TX0_D1N: J5.47 J21.21
MIPI_DSI_TX0_D1P: J5.45 J21.20
MIPI_DSI_TX0_D2N: J5.59 J21.18
MIPI_DSI_TX0_D2P: J5.57 J21.17
MIPI_DSI_TX0_D3N: J5.63 J21.30
MIPI_DSI_TX0_D3P: J5.61 J21.29
MIPI_DSI_TX1_CLKN: J5.27 J22.24
MIPI_DSI_TX1_CLKP: J5.25 J22.23
MIPI_DSI_TX1_D0N: J5.17 J22.27
MIPI_DSI_TX1_D0P: J5.15 J22.26
MIPI_DSI_TX1_D1N: J5.21 J22.21
MIPI_DSI_TX1_D1P: J5.19 J22.20
MIPI_DSI_TX1_D2N: J5.33 J22.18
MIPI_DSI_TX1_D2P: J5.31 J22.17
MIPI_DSI_TX1_D3N: J5.37 J22.30
MIPI_DSI_TX1_D3P: J5.35 J22.29
OTG0_DM: D30.2 J19.A7(DN1) J19.B7(DN2) R133.1
OTG0_DP: D31.2 J19.A6(DP1) J19.B6(DP2) R134.1
PCIE20_CLKREQn_M0: J7.37 ; also on sheet 13
PCIE20_PERSTn_M0: J7.59 ; also on sheet 13
PCIE20_REFCLKN: J4.54 ; also on sheet 13
PCIE20_REFCLKP: J4.52 ; also on sheet 13
PCIE20_RXN: J4.48 ; also on sheet 13
PCIE20_RXP: J4.46 ; also on sheet 13
PCIE20_TXN: J4.44 ; also on sheet 13
PCIE20_TXP: J4.42 ; also on sheet 13
PCIE20_WAKEn_M0: J7.39 ; also on sheet 13
PCIE_PWR_EN: J4.43 ; also on sheet 13
PHY1_LED1: J17.14(YELA) R116.1 U16.33(LED1)
PHY1_LED2: J17.11(GRLA) R117.1 U16.34(LED2)
PHY_CLKOUT125: R112.2 U16.35(CLKOUT)
PWM2_M0: J5.8 ; also on sheet 17
PWM3_IR: J5.7 ; also on sheet 19
PWR_3V3_EN: J6.59 R30.1
PWR_5V_EN: J4.35 R32.1
PWR_12V_EN: J4.41 R28.1
PWRON_KEY: J4.25 ; also on sheet 19
RECOVERY: J6.16 ; also on sheet 19
RESET_KEY: J4.29 ; also on sheet 19
RS485_1_A: D26.2 J13.1 R71.2 R80.1 U14.6(A)
RS485_1_B: D24.2 R73.1 R76.1 R79.1 U14.7(B)
RS485_2_A: D27.2 J14.1 R72.2 R82.1 U15.6(A)
RS485_2_B: D25.2 R74.1 R78.1 R81.1 U15.7(B)
RX8010_nIRQ1: J5.64 ; also on sheet 15
RX8010_nIRQ2: J5.62 ; also on sheet 15
SARADC_VIN1: J6.18 ; also on sheet 19
SDMMC0_CLK: J6.13 ; also on sheet 15
SDMMC0_CMD: J6.15 ; also on sheet 15
SDMMC0_D0: J6.19 ; also on sheet 15
SDMMC0_D1: J6.21 ; also on sheet 15
SDMMC0_D2: J6.23 ; also on sheet 15
SDMMC0_D3: J6.25 ; also on sheet 15
SDMMC0_DET: J6.17 ; also on sheet 15
SPKN_OUT: J4.24 ; also on sheet 14
SPKP_OUT: J4.22 ; also on sheet 14
SS_TXN: C112.1 J18.8(TX-) U19.2(D1-) U19.9(NC2)
SS_TXP: C113.1 J18.9(TX+) U19.1(D1+) U19.10(NC1)
UART1_DIR: J7.43 R75.1 U14.2(~{RE}) U14.3(DE)
UART1_RX_M0: J7.10 R69.2 U14.1(RXD)
UART1_TX_M0: J7.8 R67.2 U14.4(TXD)
UART2_RX_M0_DEBUG: J5.22 ; also on sheet 19
UART2_TX_M0_DEBUG: J5.20 ; also on sheet 19
UART3_RX_M1: J7.5 ; also on sheet 15
UART3_TX_M1: J7.3 ; also on sheet 15
UART4_RX_M1: J7.9 ; also on sheet 15
UART4_TX_M1: J7.7 ; also on sheet 15
UART6_DIR: J7.45 R77.1 U15.2(~{RE}) U15.3(DE)
UART6_RX_M0: J7.13 R70.2 U15.1(RXD)
UART6_TX_M0: J7.11 R68.2 U15.4(TXD)
UART7_RX_M0: J7.17 ; also on sheet 16
UART7_TX_M0: J7.15 ; also on sheet 16
UART9_RX_M1: J7.21 ; also on sheet 16
UART9_TX_M1: J7.19 ; also on sheet 16
USB2_HOST2_DM: J7.74 R126.1
USB2_HOST2_DP: J7.72 R125.1
USB2_HOST3_DM: J7.68 R142.2
USB2_HOST3_DP: J7.66 R141.2
USB3_HOST1_DM: J4.80 R136.2
USB3_HOST1_DP: J4.78 R137.2
USB3_HOST1_SSRXN: J4.60 J18.5(RX-) U18.2(D1-) U18.9(NC2)
USB3_HOST1_SSRXP: J4.58 J18.6(RX+) U18.1(D1+) U18.10(NC1)
USB3_HOST1_SSTXN: C112.2 J4.64
USB3_HOST1_SSTXP: C113.2 J4.62
USB20_HOST_PWR_EN: J7.67 R140.1
USB20_OTG_PWR_EN: J4.37 R149.1
USB30_HOST_PWR_EN: J5.14 R146.1
USB OTG: C123.1 C124.1 J19.A4(VBUS1) J19.A9(VBUS2) J19.B4(VBUS4) J19.B9(VBUS3) R148.1 U24.1(OUT)
USB_OTG0_DM: J6.6 R133.2
USB_OTG0_DP: J6.4 R134.2
USB_OTG0_ID: J6.10 R135.2
USB_OTG0_VBUSDET: J6.12 R148.2 R150.1
USER_LED: J5.6 ; also on sheet 19
WLAN_PWR_EN: J4.45 R128.1
N15599533: R96.2 U16.25(RXD0)
N15599537: R97.2 U16.24(RXD1)
N15599541: R99.2 U16.23(RXD2)
N15599545: R100.2 U16.22(RXD3)
N15599549: R101.2 U16.27(RXC)
N15599553: R102.2 U16.26(RXCTL)
N15599792: R90.2 R91.1 R93.1 R94.1 R95.1
N15600759: R106.2 R107.1 R108.1 R109.1
N15600826: R110.2 R111.2 U16.31(INTB)
N15601838: C81.1 U16.37(XTAL_OUT) Y1.1
N15601846: C82.1 U16.36(XTAL_IN) Y1.3
N15602173: D28.2 R119.2 R120.2 U16.12(PHYRSTB)
N15602572: R118.1 U16.32(LED0)
N15602600: R117.2 R121.2 R122.1
N15603170: C83.1 J17.1(CT)
N15605512: R98.1 U16.39(RSET)
N15605755: C77.1 C78.1 R89.1 R92.1 U16.28(DVDD_RG)
N15611443: C116.1 R140.2 U21.4(EN)
N15611553: R143.1 U21.3(ISET)
N15653247: C122.1 R149.2 U24.4(EN)
N15653357: R152.1 U24.3(ISET)
N15653957: C119.1 R146.2 U23.4(EN)
N15654067: R147.1 U23.3(ISET)
N15752445: L9.1 U25.G1(20) U25.G2(21) U25.G3(22) U25.G4(23)
N15772454: J22.14 R161.2
N15774097: J21.14 R160.2
N15980269: J13.2 R73.2
N17430242: R33.1 U7.3(ISET)
N17430314: C44.1 R32.2 U7.4(EN)
N17443353: R31.1 U6.3(ISET)
N17443371: C41.1 R30.2 U6.4(EN)
N17444423: C38.2 Q5.1(GATE) Q6.3(COLLECTOR) R27.2
N17444523: Q6.1(BASE) R28.2 R29.1
N17466585: L4.1 U16.30(REG_OUT)
N17633217: C117.1 U22.3(XOUT) Y2.1
N17633237: C118.2 U22.4(XIN) Y2.3
N17633305: R144.2 U22.16(RESET#/CDP)
N17633317: R145.2 U22.18(PSELF)
N17695706: C133.1 R171.2 U28.4(EN) U30.4(EN)
N17695791: R174.1 U30.3(ISET)
N17695827: R173.1 U28.3(ISET)
N17697466: J17.13(YELC) R114.1
N17701231: J14.2 R74.2
N17702194: J15.3 R81.2
N17702199: J15.4 R82.2
N17702222: J15.2 R80.2
N17702231: J15.1 R79.2
N17728858: D22.1 R71.1
N17729021: D23.1 R72.1
N17748815: Q5.2(SOURCE) R26.2
N17770939: R141.1 U22.15(DPU)
N17770942: R142.1 U22.14(DMU)
N18056005: C107.2 Q7.1(GATE) R127.2 R128.2
N18056634: C104.1 C105.1 U17.2(RF0)
N18056637: C104.2 C106.1 CN1.1
N18057325: R126.2 U17.7(D-)
N18057335: R125.2 U17.6(D+)
N18111918: C130.1 R170.2 U29.4(EN) U31.4(EN)
N18111989: R175.1 U31.3(ISET)
N18112037: R172.1 U29.3(ISET)
N18173560: J19.C1(SH1) J19.C2(SH2) J19.C3(SH3) J19.C4(SH4) L8.1
N18175084: D29.3 R135.1
N18353176: J17.12(GRLC) R115.1

Not connected (* = marked no-connect by the designer): J4 33* 47* 51* 53* 55* 57* 59* 61* 63* 65* 68* 69* 70* 71* 72* 74* 75* 77* 79*; J6 22* 24* 26* 28* 32* 34* 36* 38* 43* 45* 47* 49* 50* 52* 54* 56* 63* 67* 71* 73* 77*; J7 4* 6* 14* 16* 18* 20* 22* 24*; J18 14(NC1)* 15(NC2)* 17(NC4)* 18(NC5)*; J19 A8(SBU1)* B8(SBU2)*; U17 3(RF1)* 4(XIN)* 9(SUSPEND)* 10(WO_WLAN)* 11(BT_PCM_CLK)* 12(BT_PCM_SYNC)* 13(BT_PCM_OUT)* 14(BT_PCM_IN)*; U22 2(NC1)* 13(LED3/SCL)* 17(NC2)* 19(VDD5)* 21(LED4/SDA)* 22(LED1)* 23(LED2)* 24(PWREN#)*; U25 14*

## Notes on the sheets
sheet 1
- WLAN & BT
- Z0=50Ω
- WLAN Power
- GPIO0_D5
sheet 2
- 野火_EBF RK3566 BTB 底板 原理图
- 目录
- Page 1
- Content
- Page 2
- Historic Version
- Page 3
- POWER DIAGRAM
- Page 4
- DC IN/POWER/FAN
- Page 5
- POWER OUT PORT
- Page 6
- BTB Connector
- Page 7
- Button/FLASH/IR/DEBUG/LED
- Page 8
- SD/RTC/RS232
- Page 9
- WIFI&Bluetooth
- Page 10
- ETH
- Page 11
- USB PORT
- Page 12
- HDMI PORT
- Page 13
- MIPI DSI/eDP1.3/TP_PORT
- Page 14
- MIPI CSI PORT
- Page 15
- eDP_1.3/TP_PORT
- Page 16
- MINI PCIE_PORT
- Page 17
- AUDIO PORT
- Page 18
- RS485 PORT
sheet 3
- 历史版本
- 版本号
- 日期
- 设计
- 描述
- V1.0
- 2023-03-07
- ghs
- 初始版本
sheet 4
- POWER DIAGRAM
- VCC12V_EDP
- PMOS
- EDP Power
- VCC12V_OUT
- PMOS
- Power OUT
- Switch
- EDP_PORT
- OCP：1A
- Switch
- MIPI_PORT
- DC-DC
- OCP：1A
- VCC3V3_SYS
- 3.3V 3A
- Switch
- Power OUT
- OCP：1A
- ETH
- UART7
- RS232
- SYS_Switch
- VDD_3V3
- WIFI&BT
- UART9
- RS485_1
- OCP：2A
- LED
- RTC
- RS485_2
- IR PORT
- HDMI_PORT
- USB2.0 HUB PHY
- Switch
- MIPI_CSI
- OCP：1A
- Switch
- MIPI_DSI_1
- DC IN
- DC-DC
- OCP：2A
- MIPI_DSI_2
- VCC5V0_SYS
- 12V 3A
- 5V 3A
- Core Top Plate
- SYS_Switch
- VDD_5V
- HDMI_PORT
- OCP：1A
- Switch
- USB2.0_PORT
- OCP：2A
- Switch
- USB3.0_OTG
- OCP：2A
- DC-DC
- VCC5V0_SYS_2
- 5V 3A
- Switch
- USB2.0_HOST
- OCP：2A
- Switch
- Power OUT
- OCP：1A
- NC
- FAN
- DC-DC
- MINIPCIE_3V3
- 3.3V 3A
- MINI_PCIE
sheet 5
- Power OutPut SW
- Power Output
- OCP：3.3V 1A
- OCP：5V 1A
- 1.5A熔断
- GPIO0_D3
- 1.8V IO
- GPIO3_C1
- 1A限流
- GPIO0_C5
- 1A限流
sheet 6
- BD ID
- Board ID:17
- BD_CH3:0.72V
- ADC值:409
- GPIO0_A6
- PWM_M0
- GPIO0_C0
- PWM4
- GPIO4_C2
- PWM5
- GPIO3_D4
- GPIO4_C3
- GPIO4_D5
- GPIO0_C5
- GPIO0_C6
- GPIO0_C7
- 1.8V
- 1.8V
- GPIO0_D3
- GPIO0_D4
- 1.8V
- GPIO0_D5
- 1.8V
- GPIO0_D6
- GPIO3_A2
- GPIO3_A4
- GPIO3_A3
- GPIO3_A6
- GPIO3_A5
- GPIO3_C5
- PWM15_IR_M0
- GPIO4_C0
- PWM11_IR_M1
- GPIO3_C6
- SDMMC2_D0_M0
- GPIO3_C7
- GPIO3_D0
- SDMMC2_D1_M0
- SDMMC2_D2_M0
- GPIO3_D1
- SDMMC2_D3_M0
- GPIO3_D2
- SDMMC2_CMD_M0
- GPIO3_D3
- SDMMC2_CLK_M0
- 1.8V
- 1.8V
- GPIO2_B2
- UART8_CTSn_M0
- 1.8V
- GPIO2_B1
- UART8_RTSn_M0
- 1.8V
- GPIO2_C6
- UART8_RX_M0
- GPIO2_A7
- 1.8V
- GPIO2_C5
- UART8_TX_M0
- 1.8V
- GPIO2_B0
- GPIO2_B5
- GPIO2_B6
- LED2
- GPIO2_B7
- EDP_TX_D2P
- LED3
- GPIO2_C0
- EDP_TX_D2N
- SPI2_CLK_M0
- GPIO2_C1
- EDP_TX_D3P
- SPI2_MISO_M0
- SPI2_MOSI_M0
- GPIO2_C2
- GPIO2_C3
- GPIO3_B6
- EDP_TX_D3N
- SPI2_CS0_M0
- GPIO2_C4
- GPIO3_C1
- GPIO3_C2
- GPIO3_B5
- GPIO3_C3
- GPIO3_A7
- GPIO3_C4
- GPIO3_B0
- GPIO3_A1
- GPIO1_A4
- GPIO1_B0
- GPIO1_B1
- GPIO1_B2
sheet 7
- RS485-1
- RS485-2
- GPIO2_B5
- GPIO2_B6
- RS485 PORT
sheet 8
- ETH
- TXC / RXC : delays 2ns
- PHY Address : 010
- IO use an external
  power supply：3.3V
- L:<200mils
  W:>60mils
- L:<200mils
  W:>60mils
- L:<200mils
- W:>60mils
- GPIO4_C2
- GPIO0_A6
sheet 9
- USB3.0 HOST & OTG
- USB2.0 HOST
- TYPE-C OTG
- HOST Power
- USB 2.0 HUB PHY
- GPIO3_A1
- 2A限流
- GPIO4_C3
- 2A限流
- GPIO0_C6
- 1A限流
sheet 10
- HDMI2.0 PORT
- KLXES15AAA1*5
sheet 11
- MIPI_DSI_TX0 PORT
- MIPI_DSI_TX1 PORT
- GPIO3_C4
- GPIO3_C2
- PWM4
- GPIO2_C3
- GPIO3_A4
- GPIO2_C4
- PWM5
- GPIO3_A3
- GPIO2_C1
- GPIO2_C2
- MIPI DSI Power
- GPIO3_D5
- GPIO1_A4
- 1A限流
- 1A限流
- 1A限流
- 1A限流
